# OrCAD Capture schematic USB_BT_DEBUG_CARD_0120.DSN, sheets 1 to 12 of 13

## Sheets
1 PAGE01 TITLE: rev: A
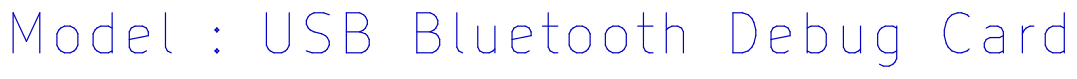
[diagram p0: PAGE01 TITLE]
2 PAGE02 INDEX
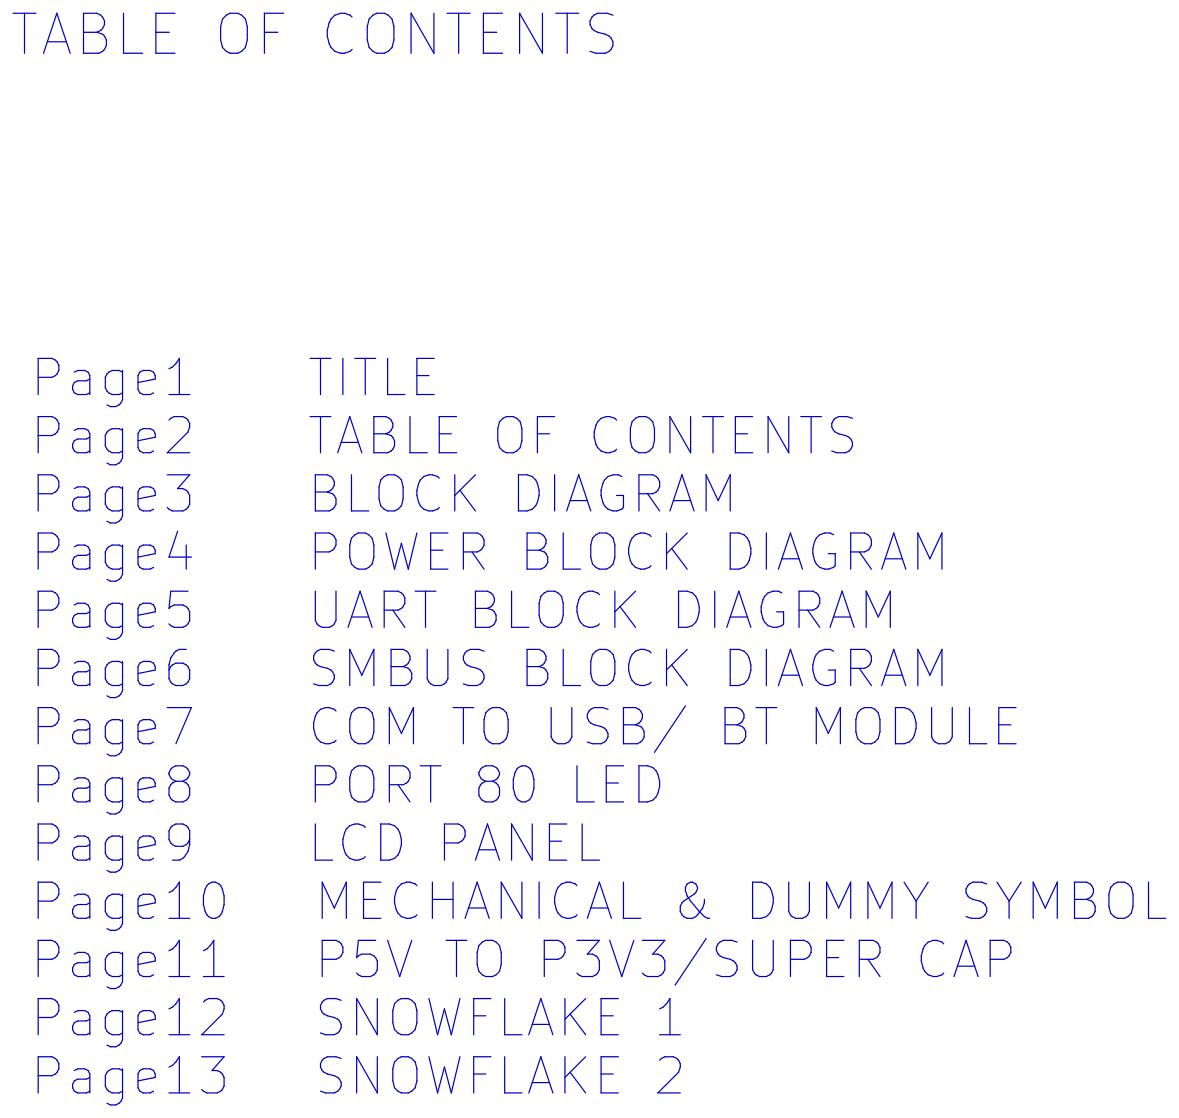
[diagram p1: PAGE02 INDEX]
3 PAGE03 BLOCK DIAGRAM
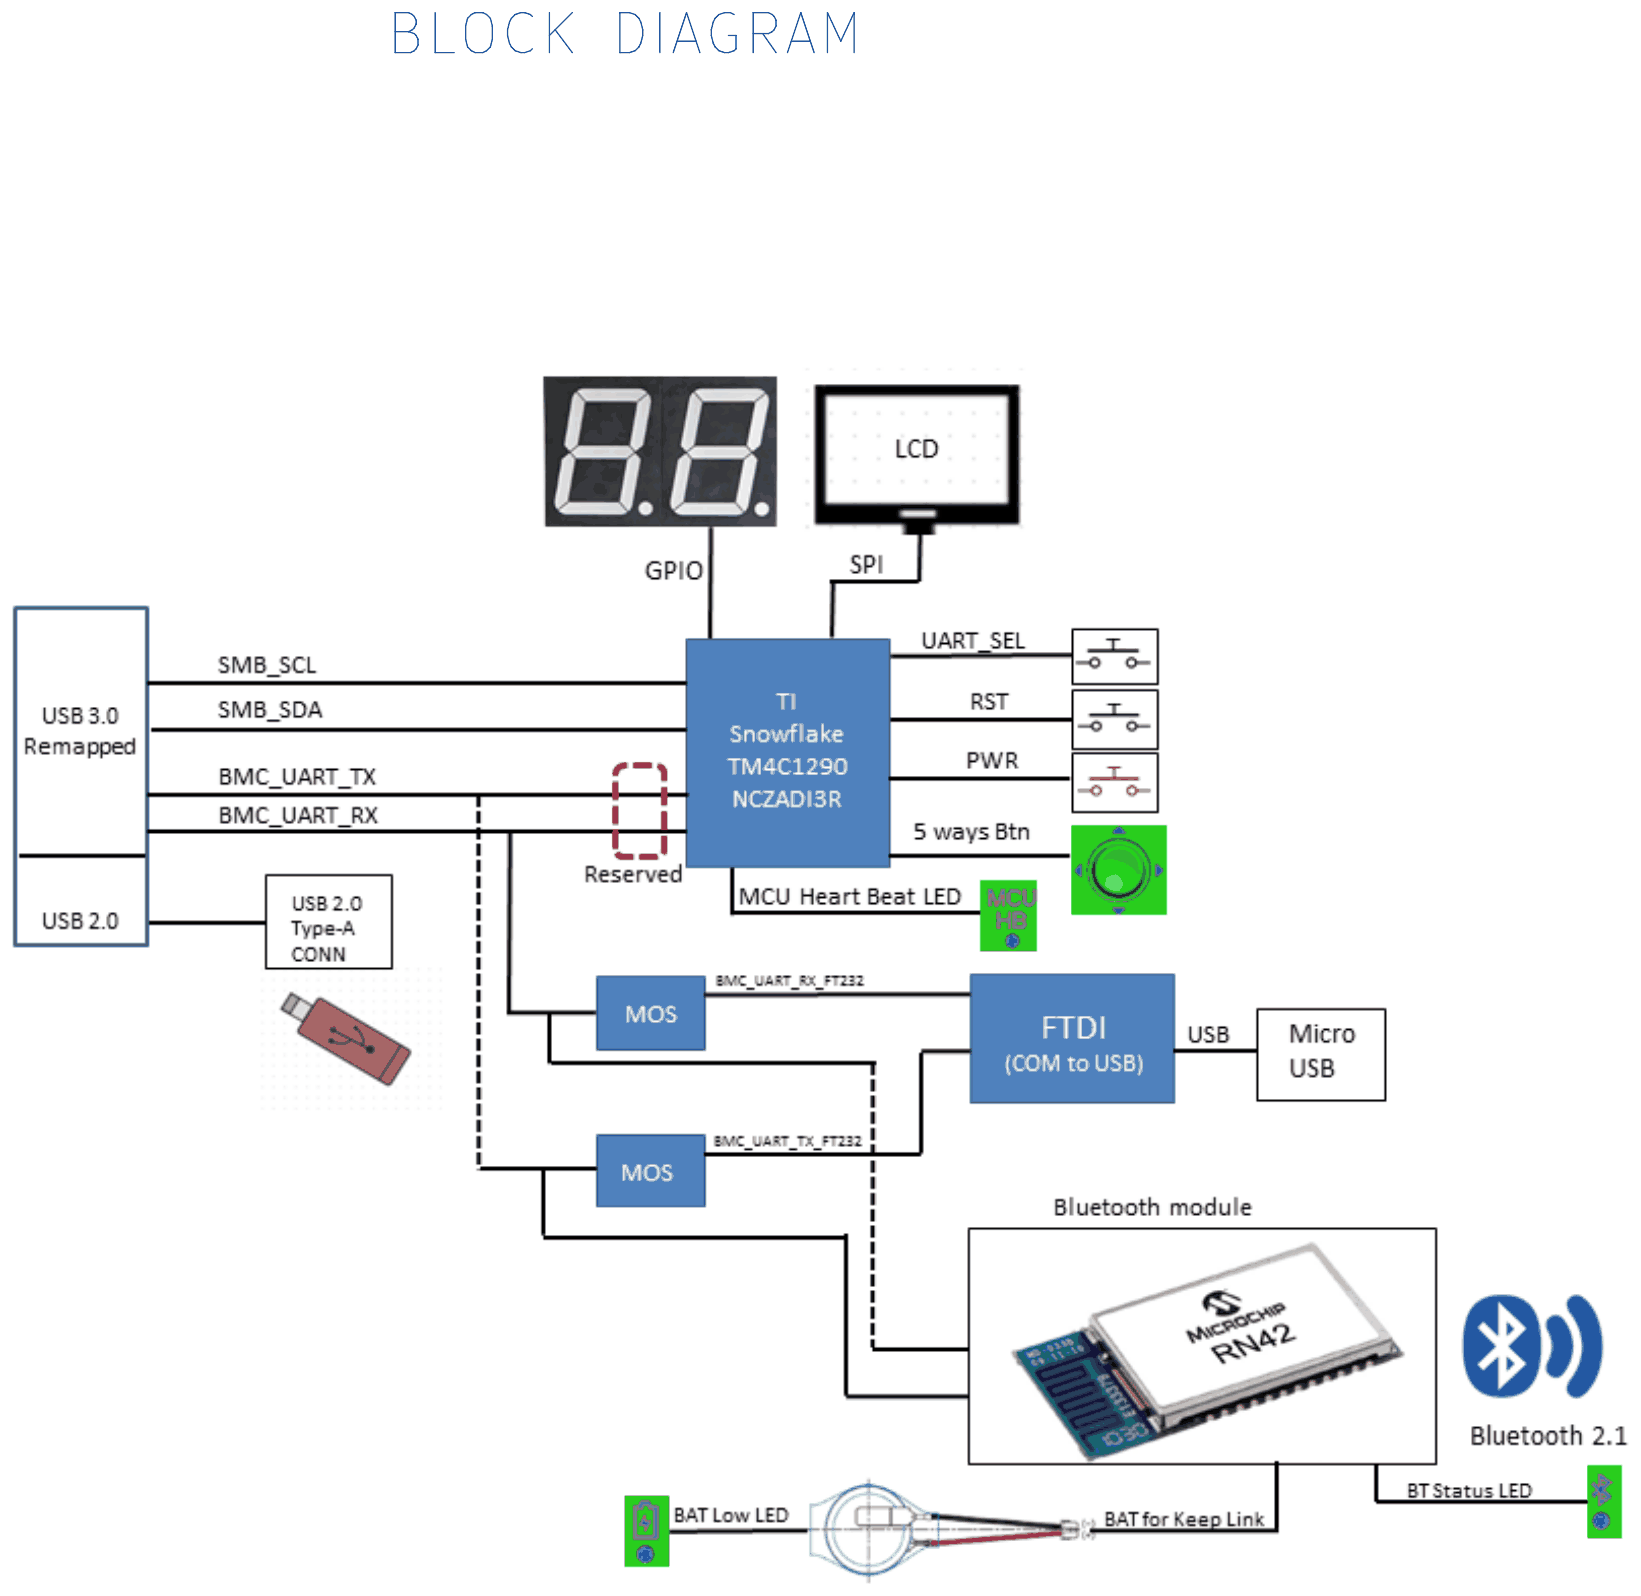
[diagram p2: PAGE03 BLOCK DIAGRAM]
4 PAGE04 POWER BLOCK DIAGRAM
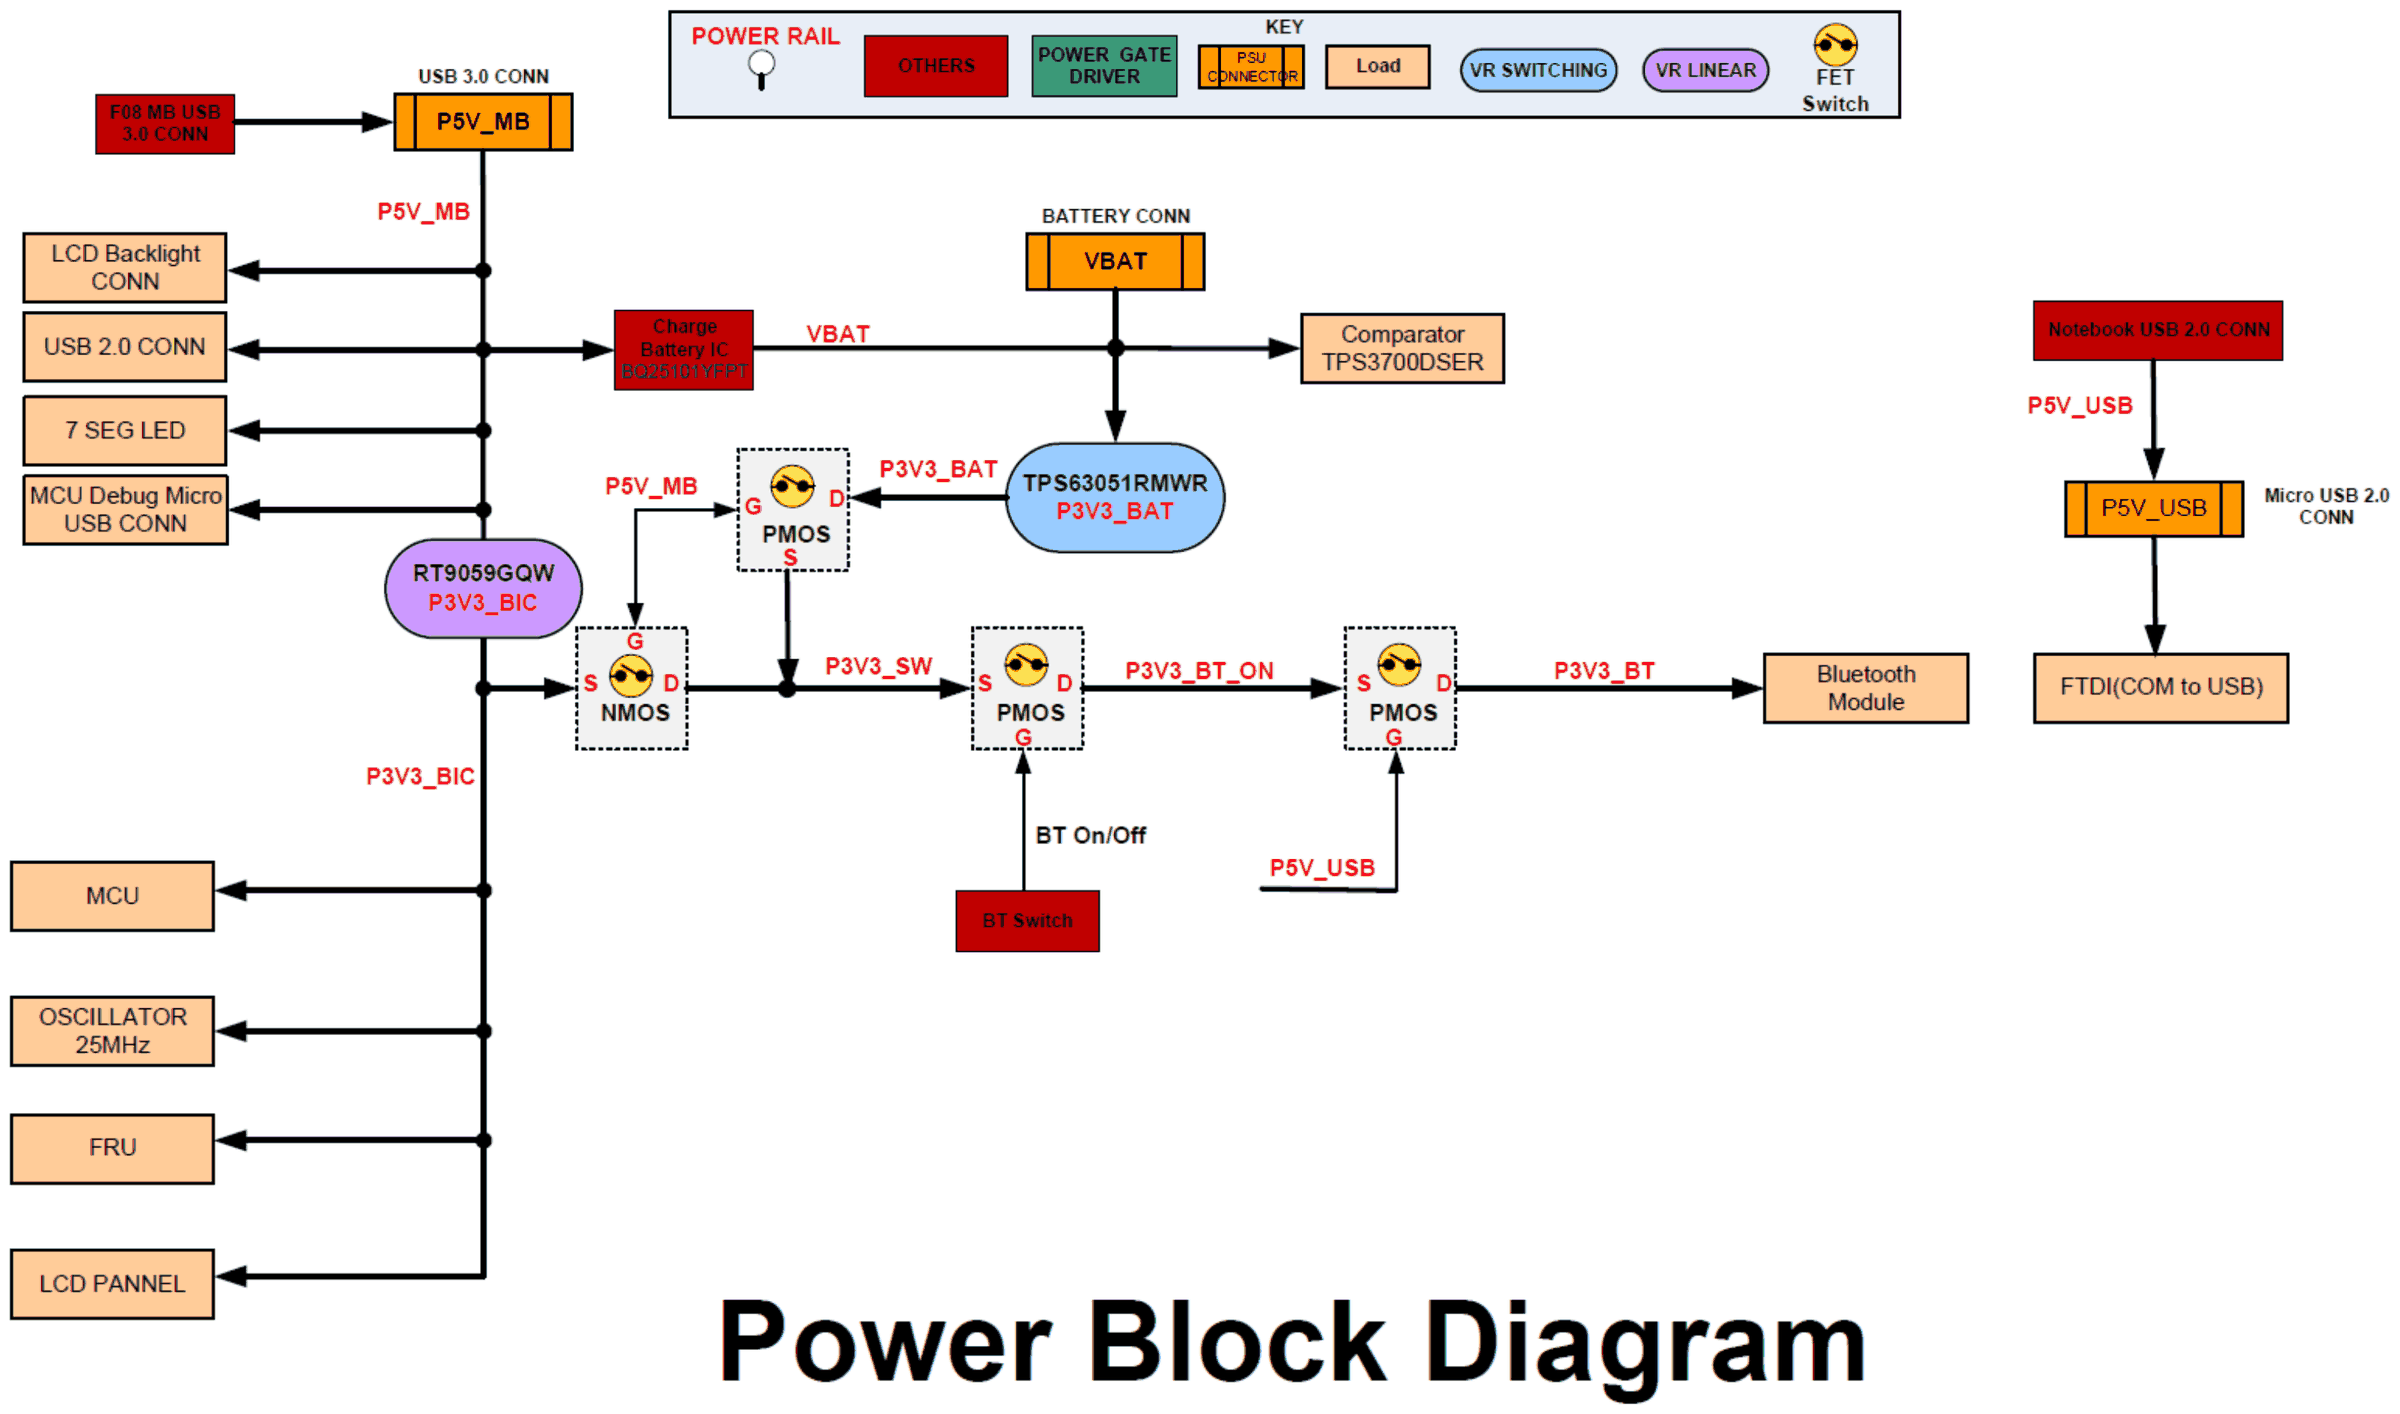
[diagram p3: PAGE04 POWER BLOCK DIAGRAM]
5 PAGE05 UART BLOCK DIAGRAM
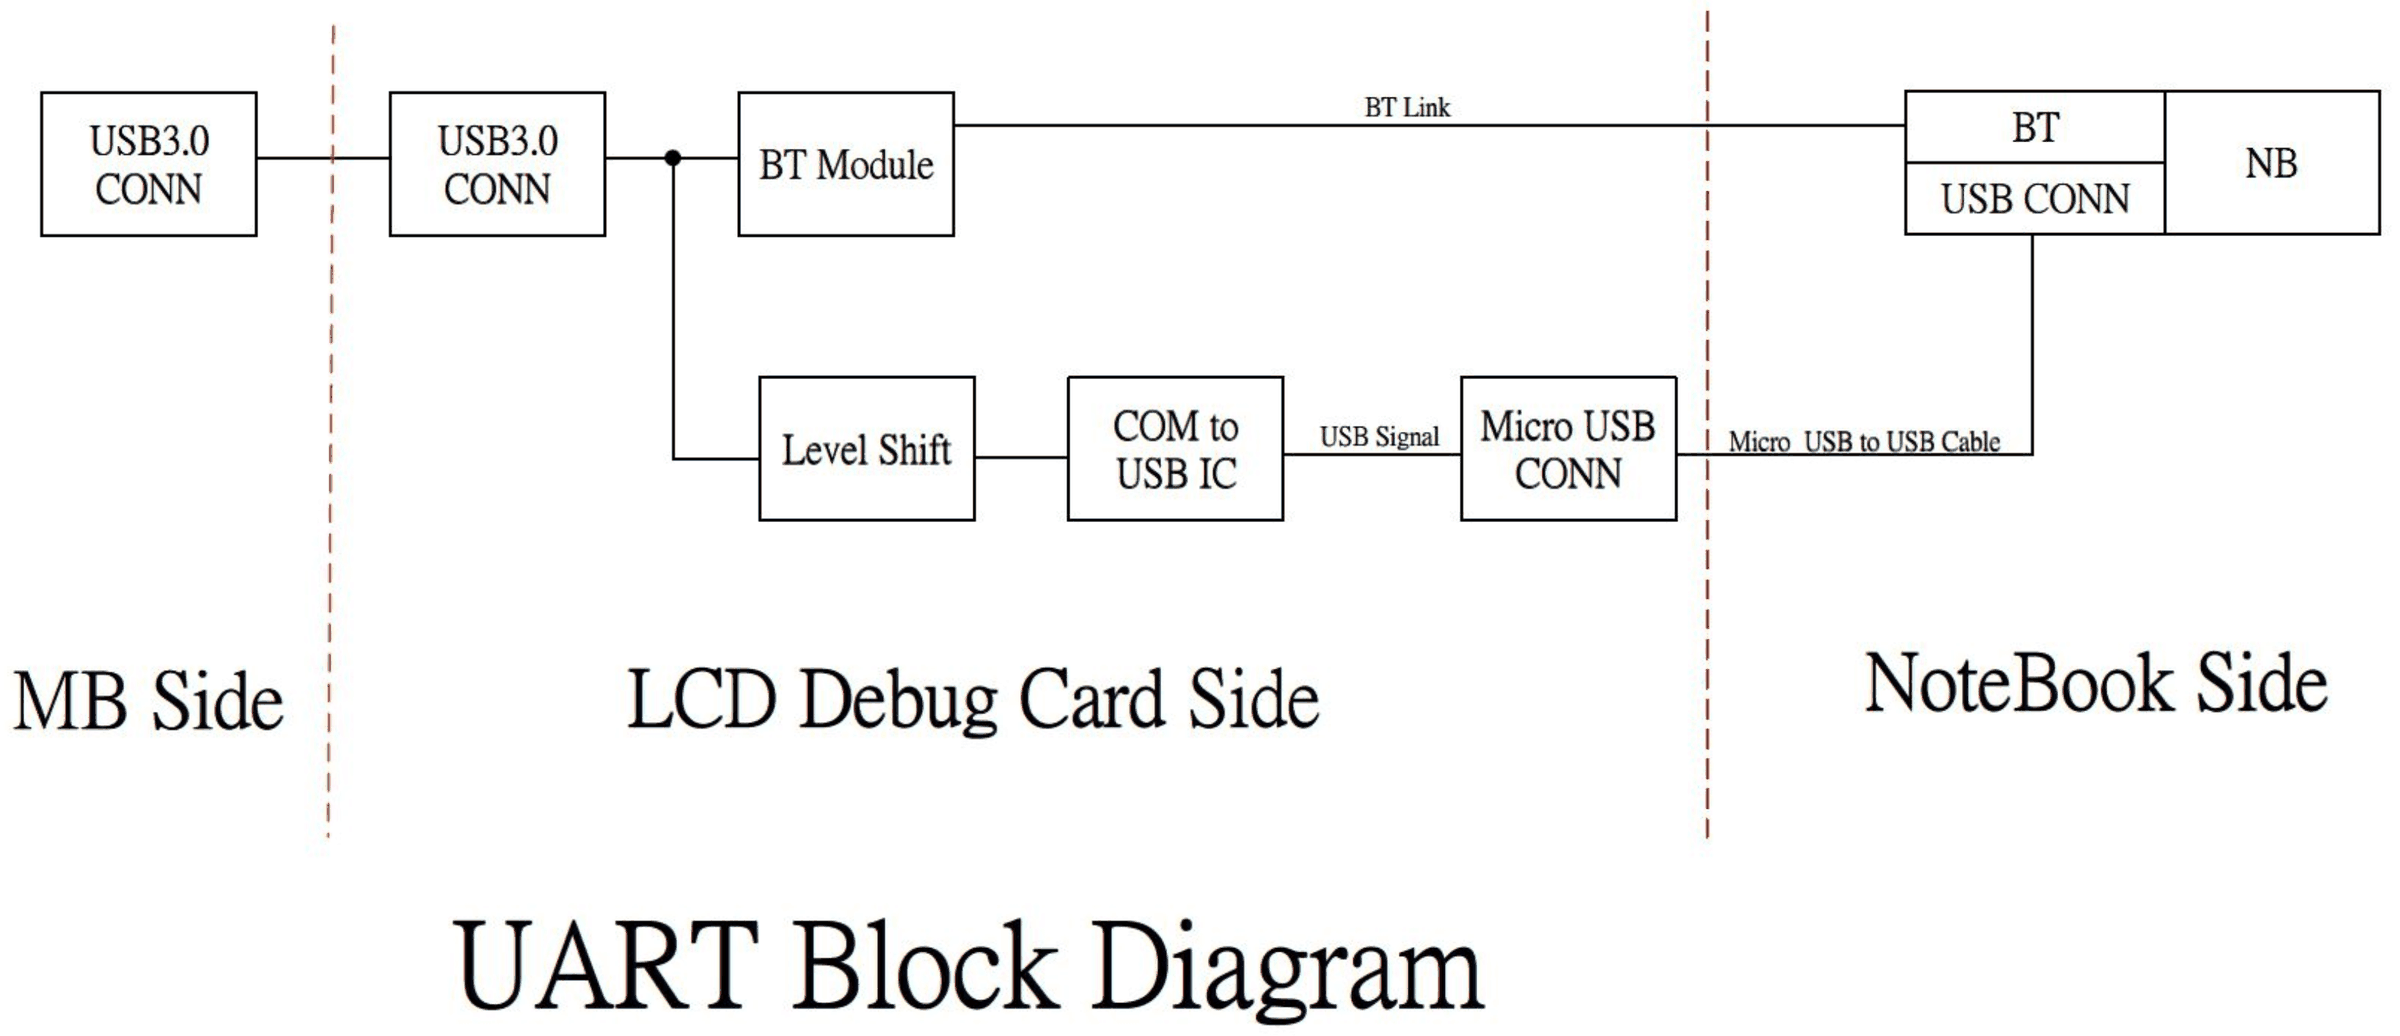
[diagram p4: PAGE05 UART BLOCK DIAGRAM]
6 PAGE06 SMBUS BLOCK DIAGRAM
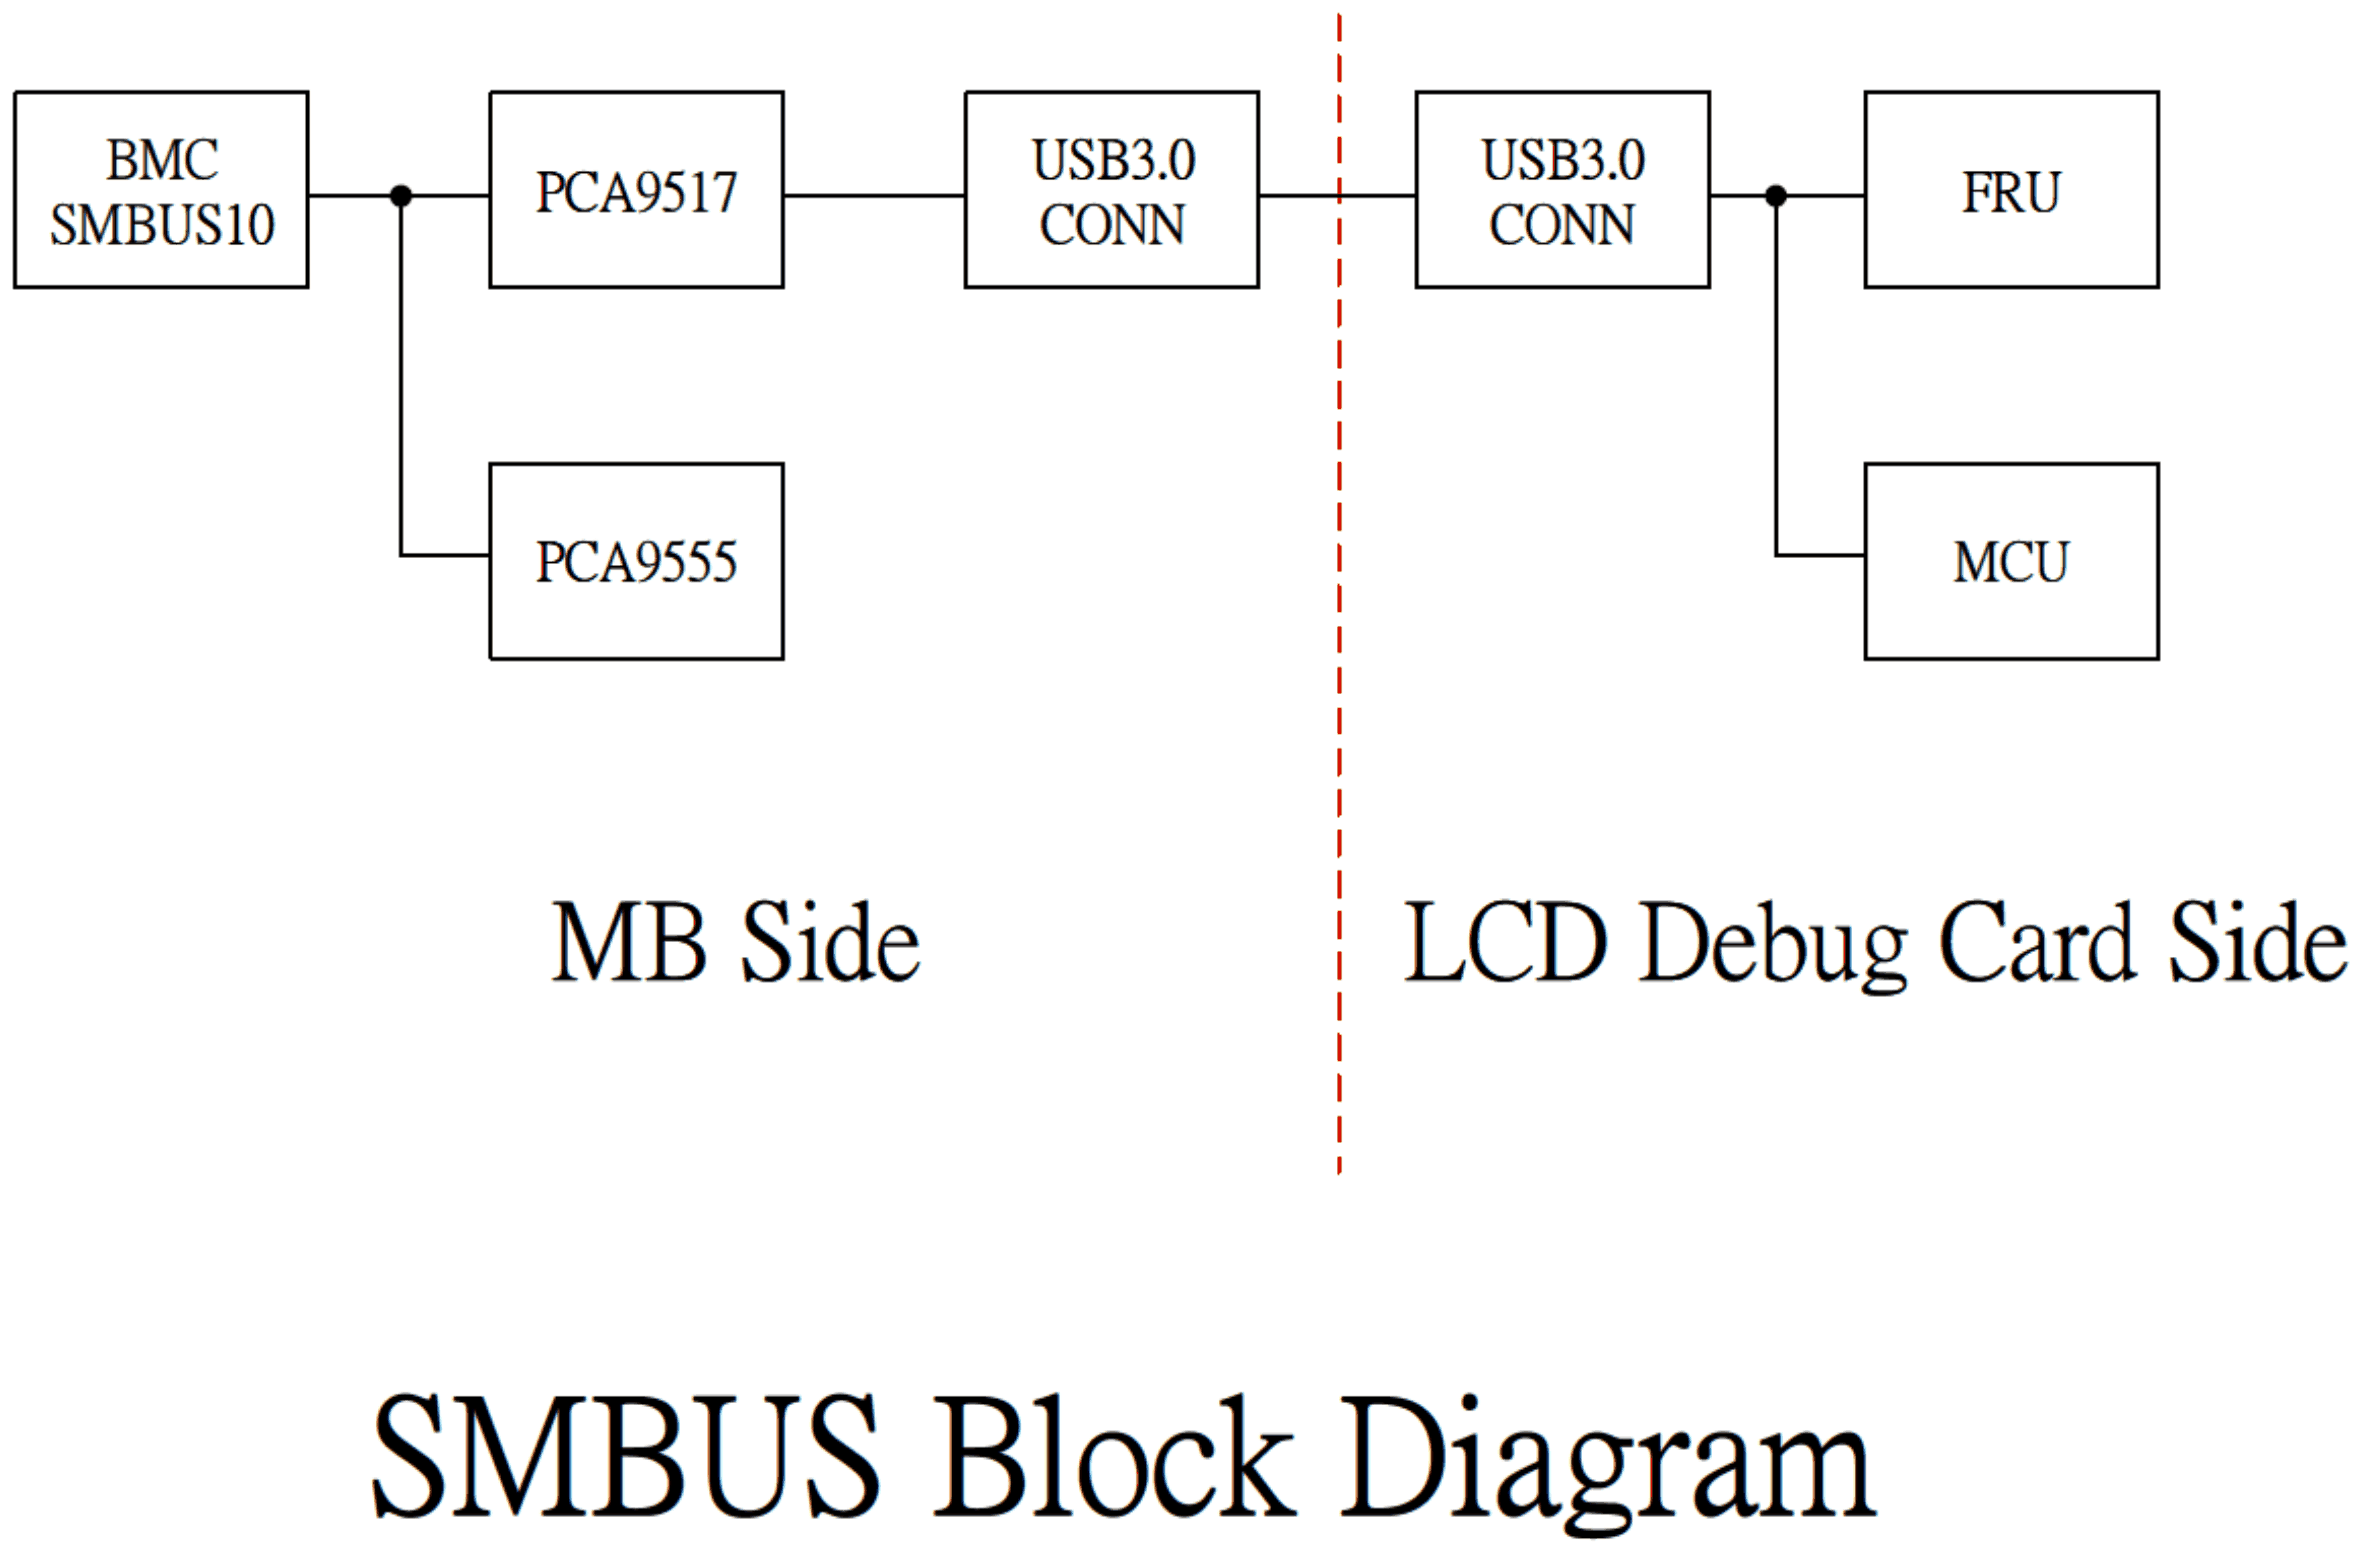
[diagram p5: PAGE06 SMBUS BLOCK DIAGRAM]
7 PAGE08 CPLD MCU: size A3
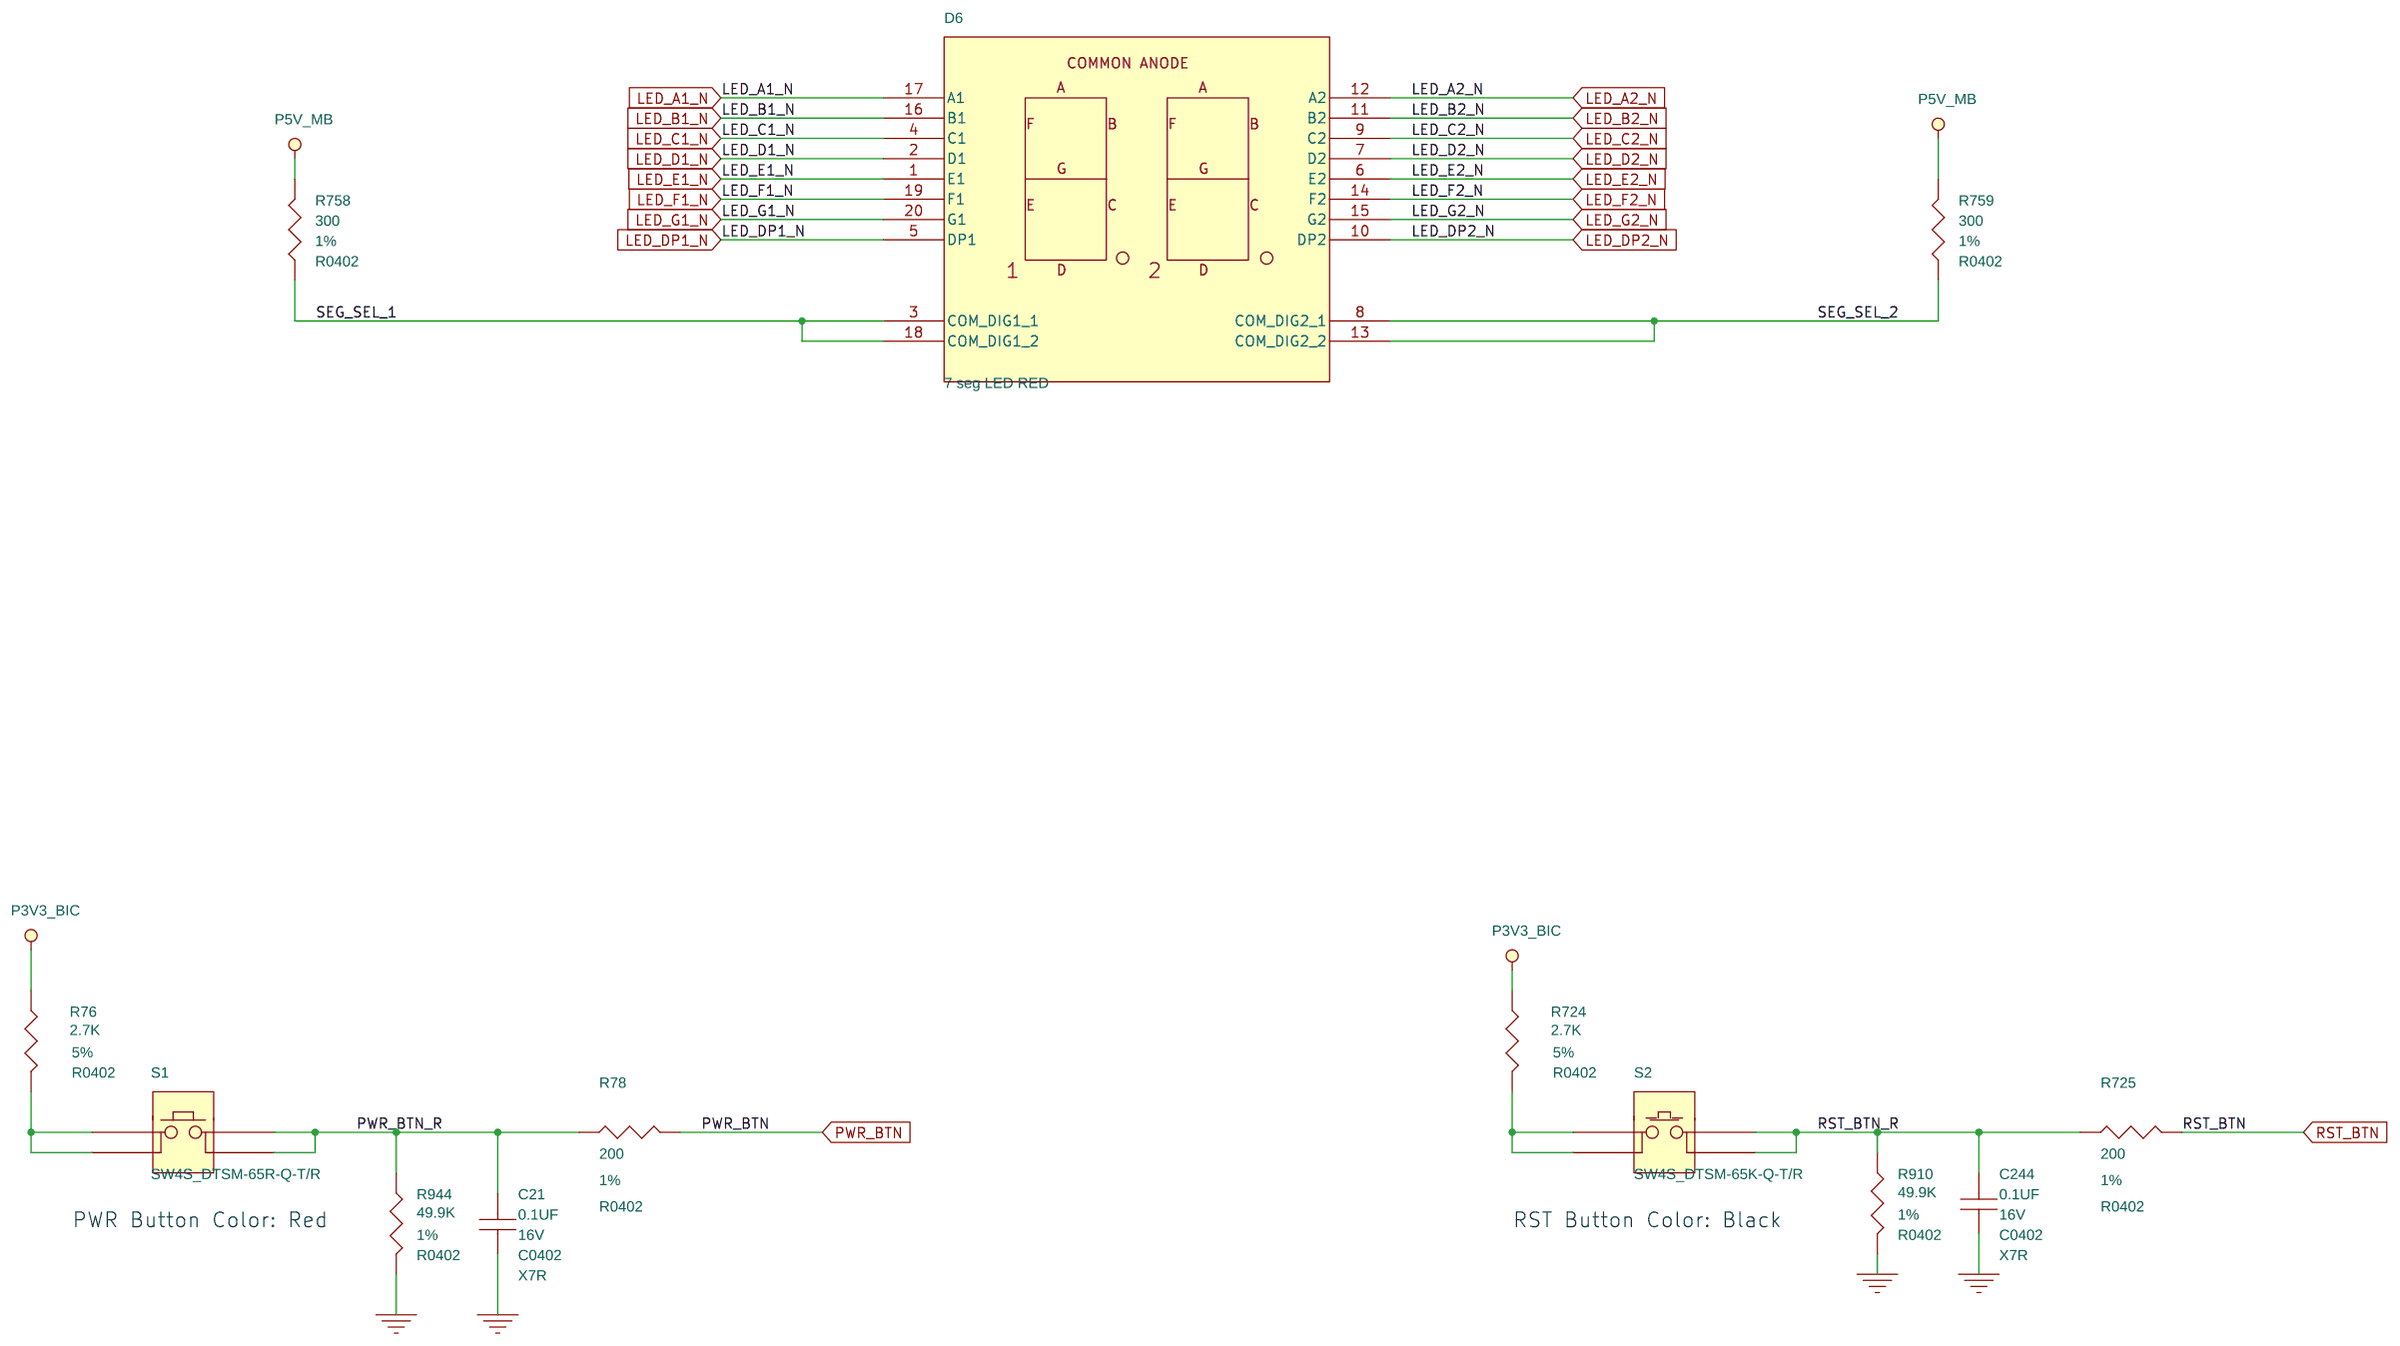
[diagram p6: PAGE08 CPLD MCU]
8 PAGE09 LCD: size A3
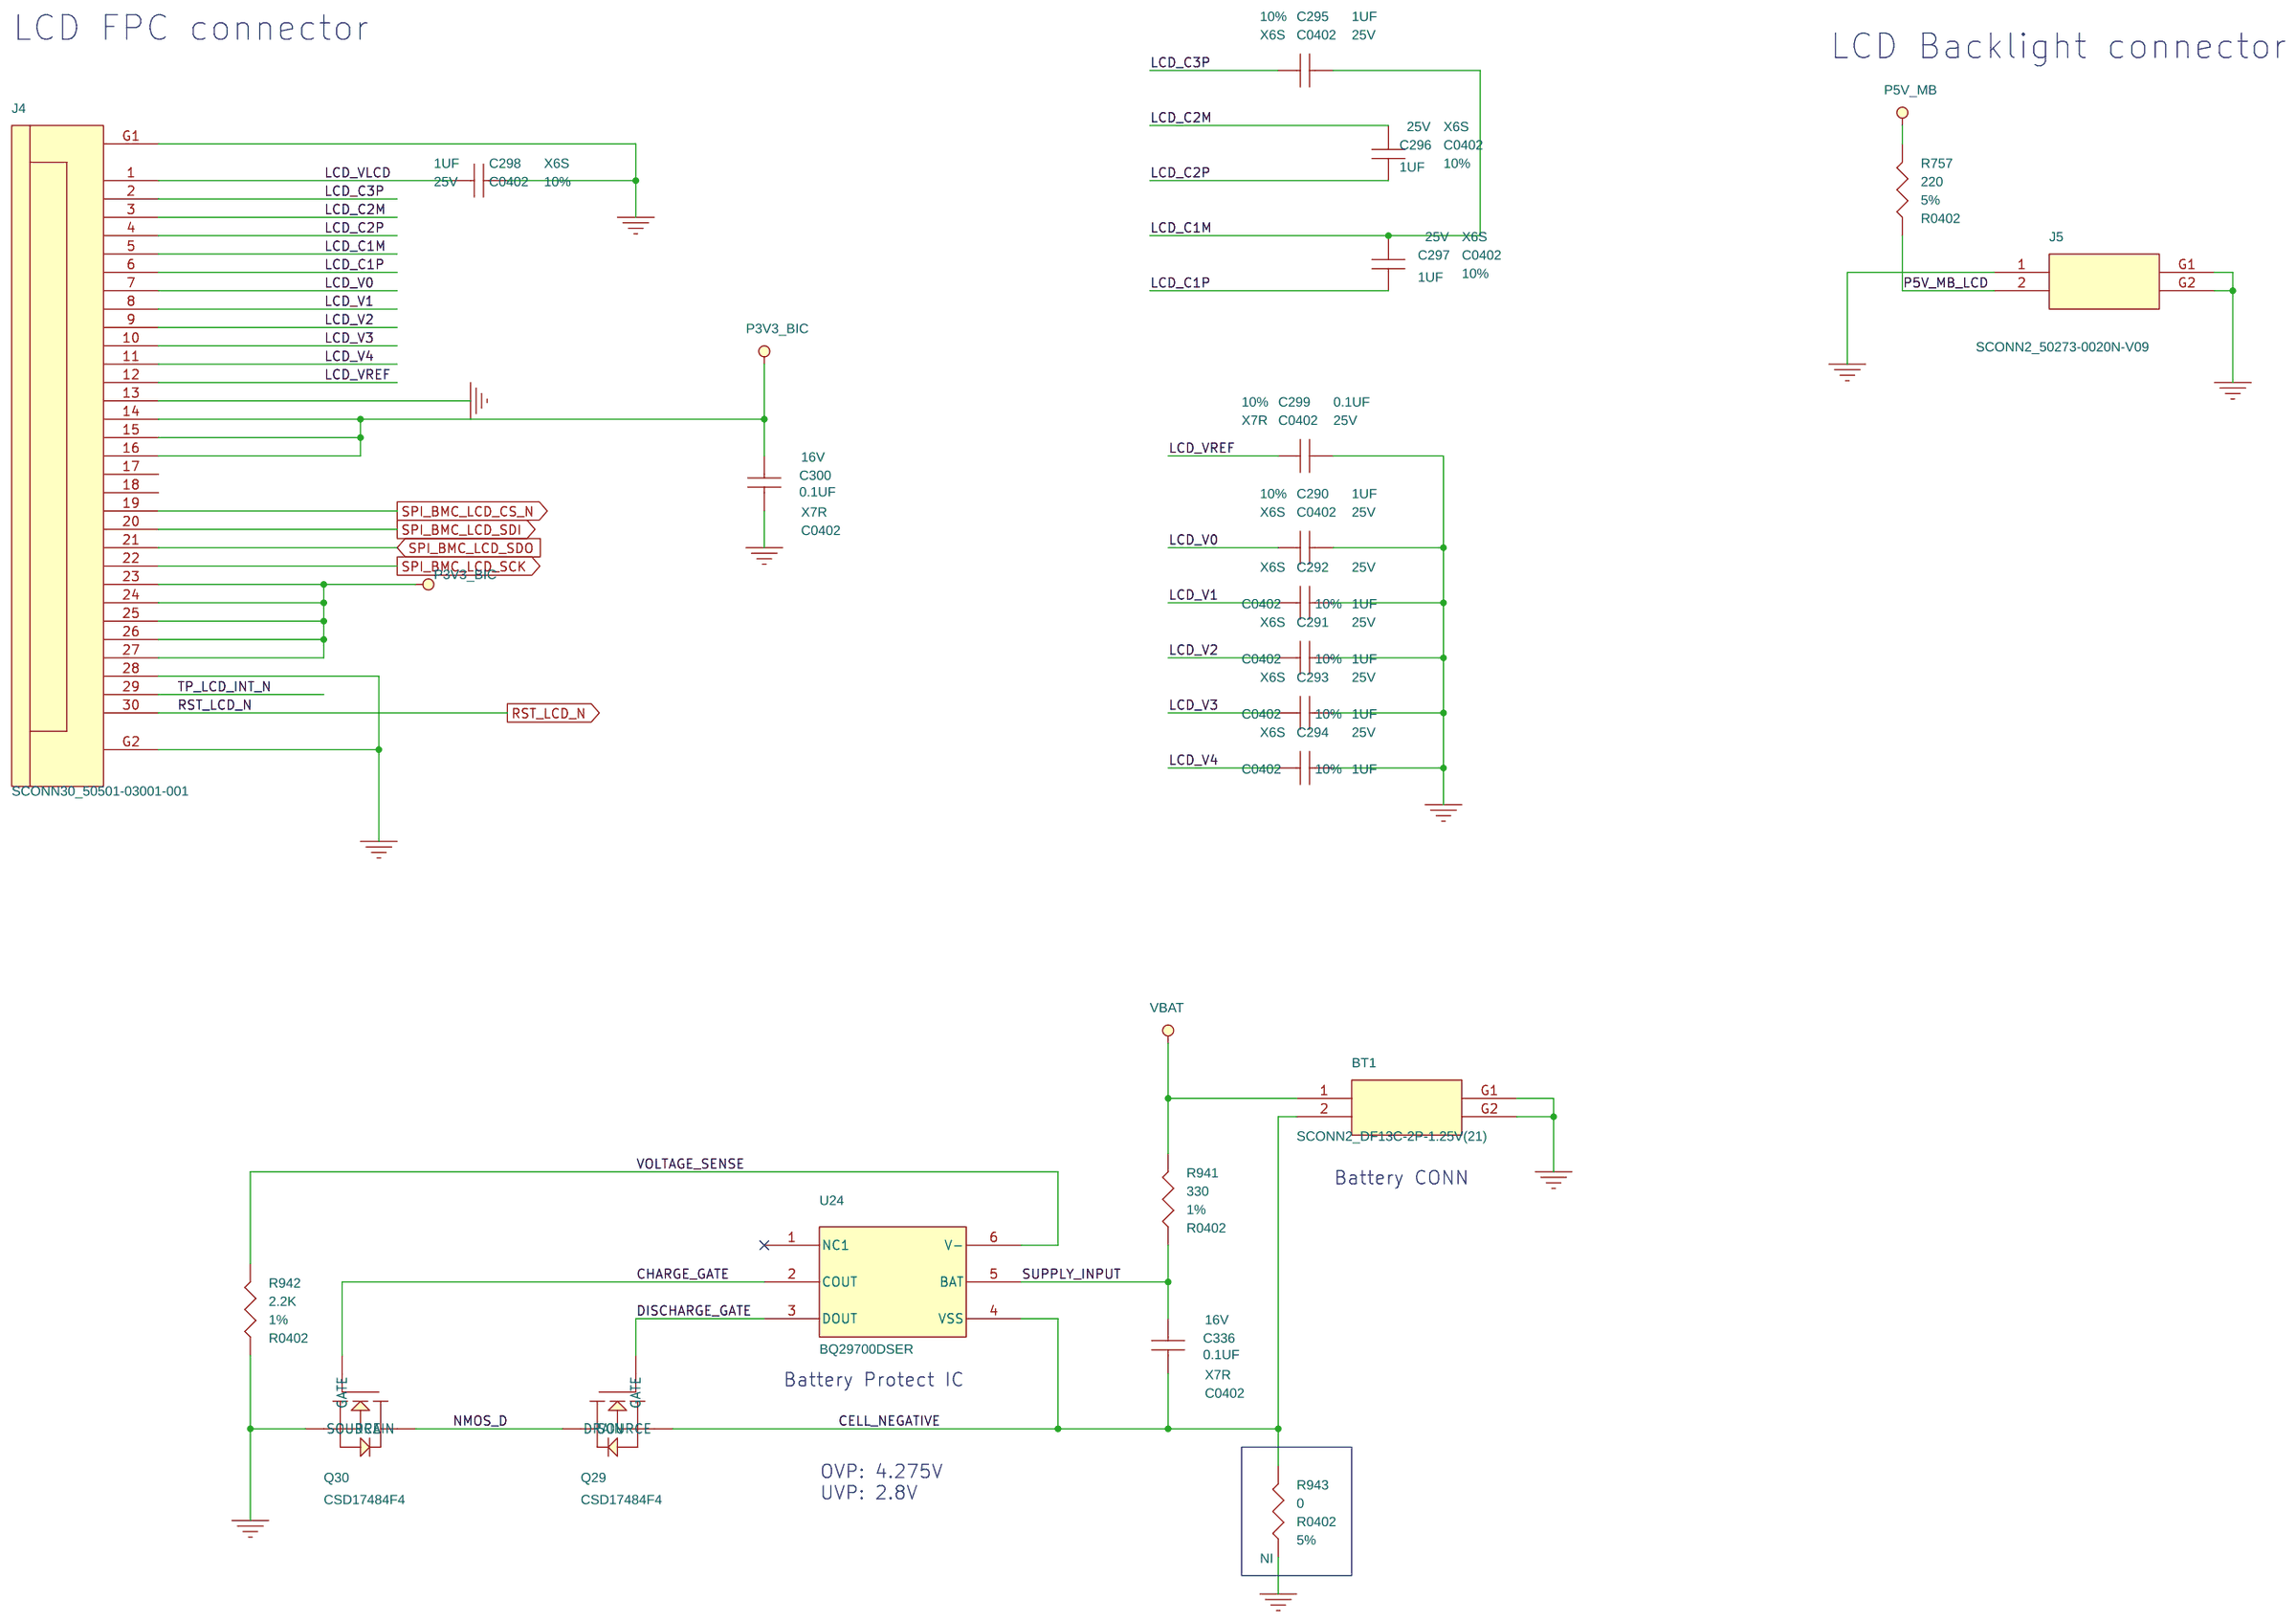
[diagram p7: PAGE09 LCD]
9 PAGE12 SNOWFLAKE1: size A3; rev: 0.01
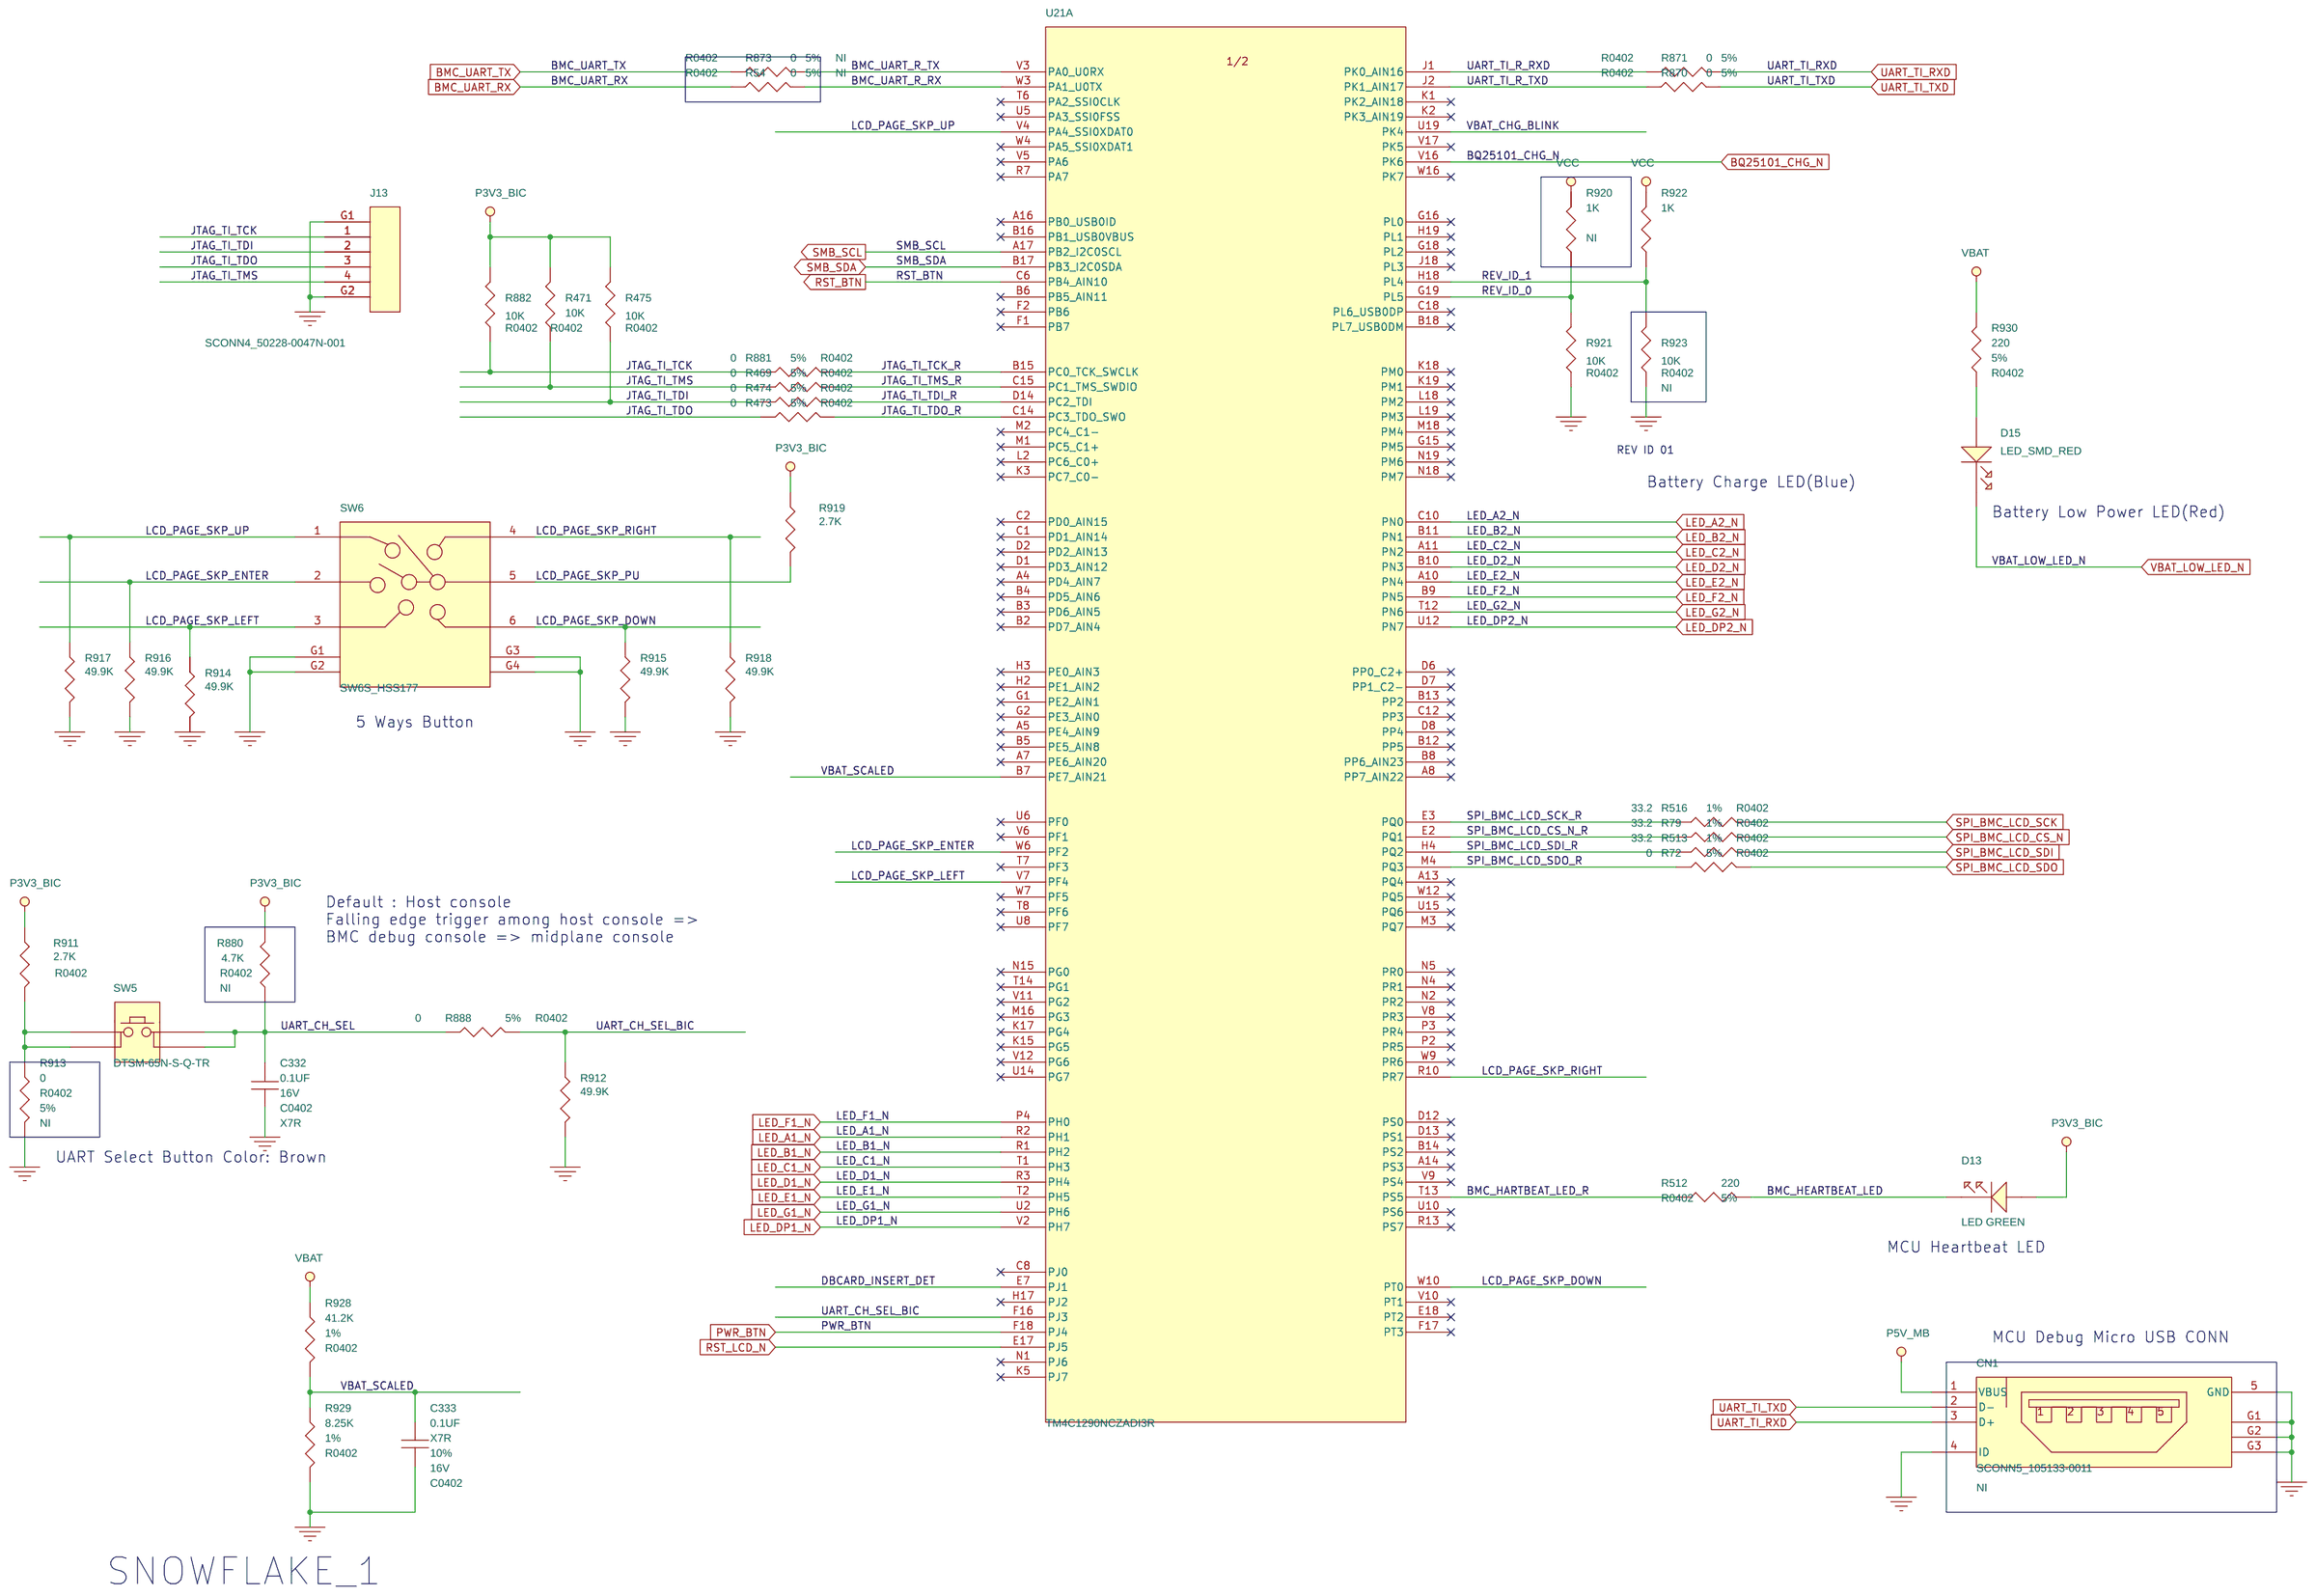
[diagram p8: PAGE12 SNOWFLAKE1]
10 PAGE13 SNOWFLAKE2: size A3; rev: 0.01
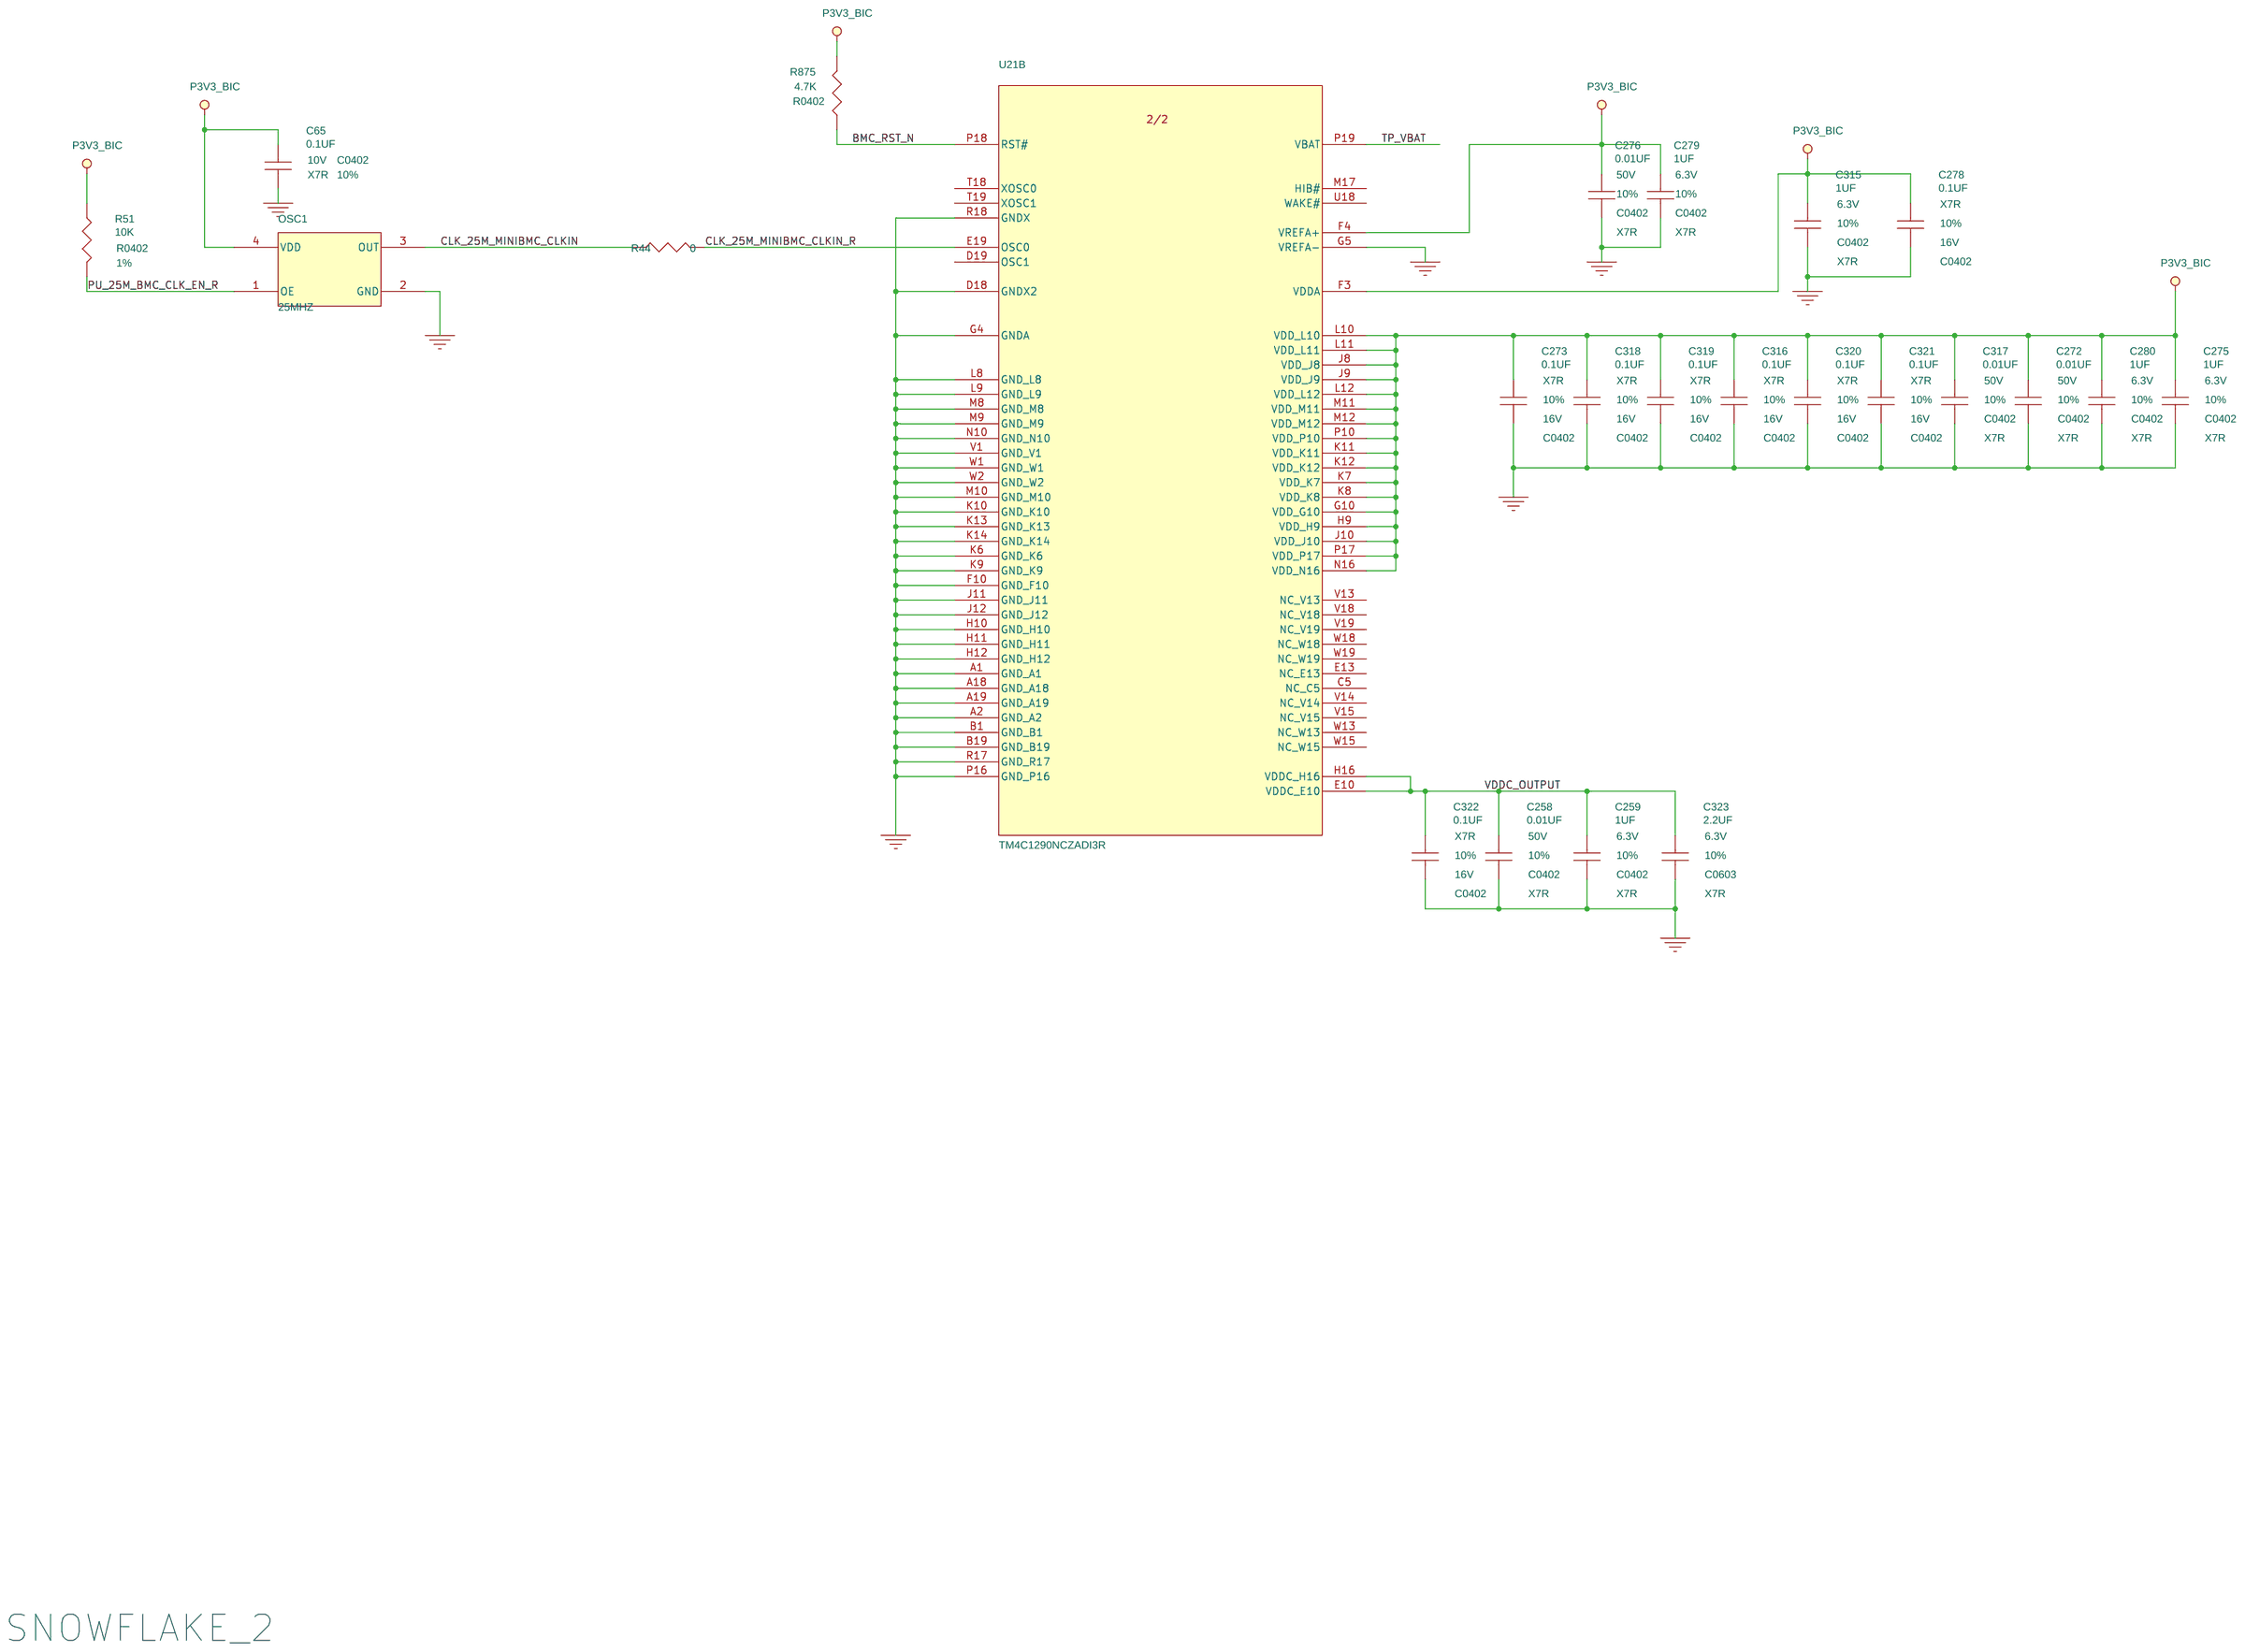
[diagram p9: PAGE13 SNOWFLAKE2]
11 PAGE10 MECHANICAL/DUMMY: size A3
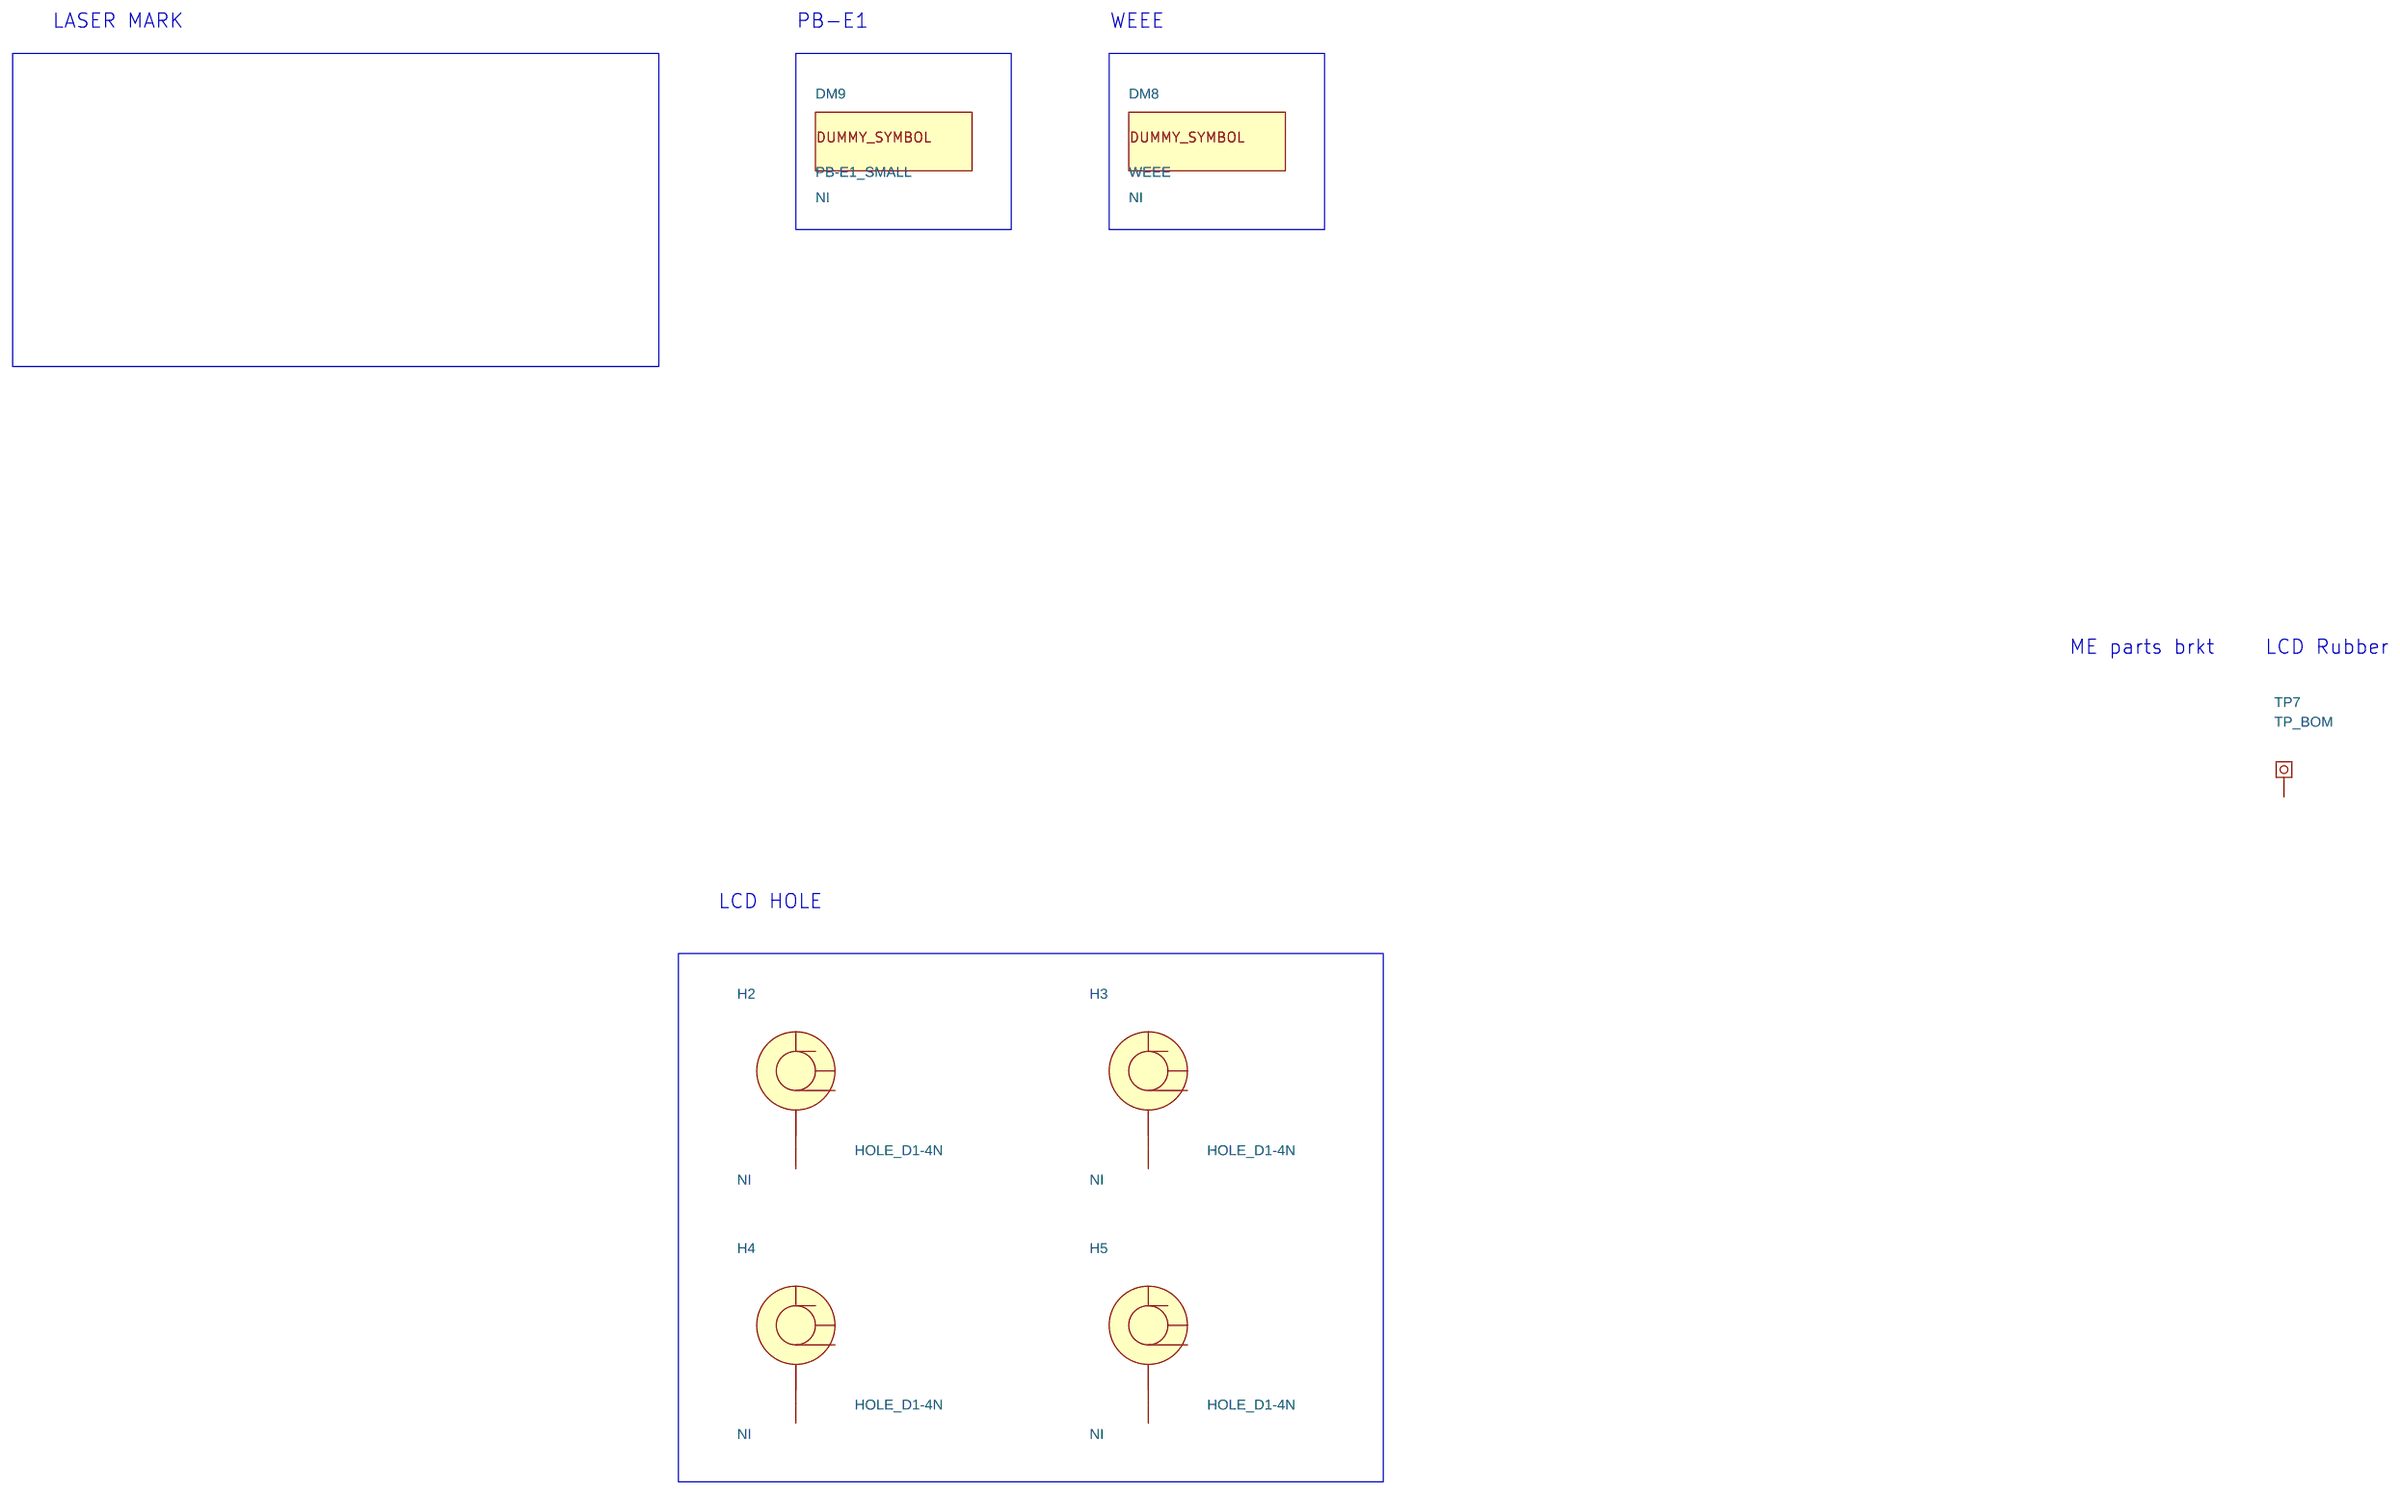
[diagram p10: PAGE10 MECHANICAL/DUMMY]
12 PAGE07 COM to USB/BT module: size A3
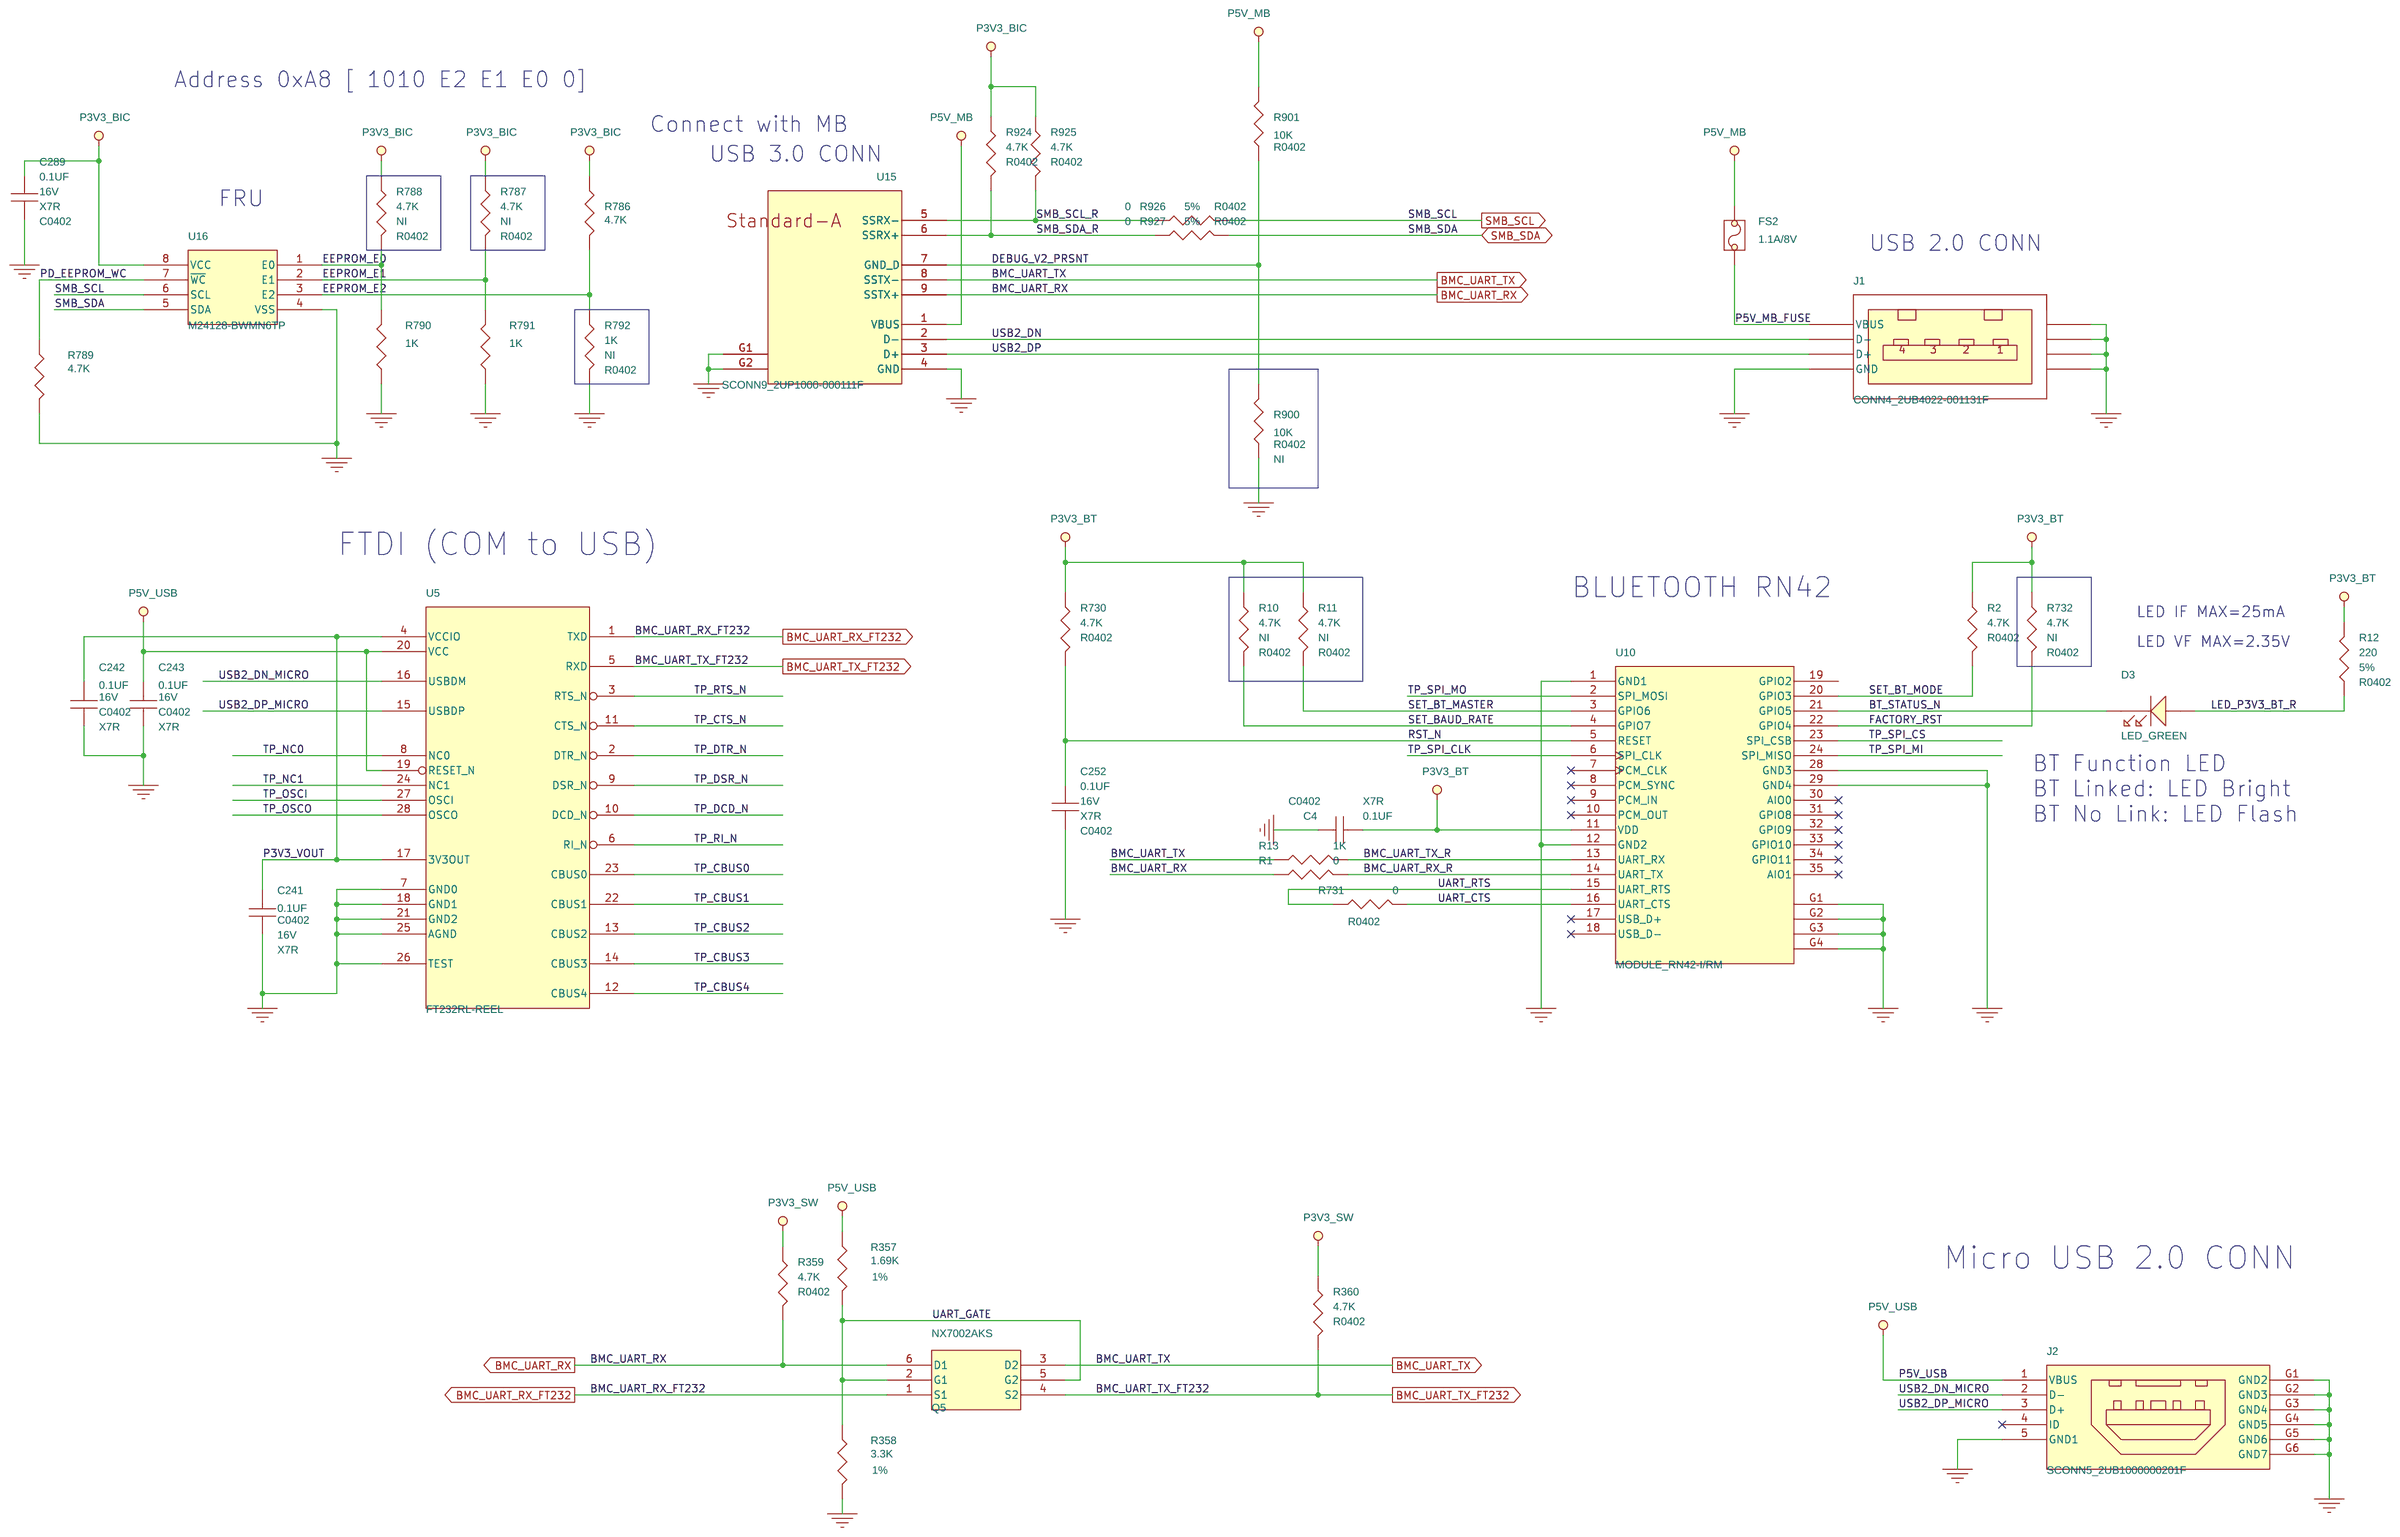
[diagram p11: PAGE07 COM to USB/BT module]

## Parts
sheet PAGE07 COM to USB/BT module
C4  0.1UF  [C0402]
C241  0.1UF  [C0402]
C242  0.1UF  [C0402]
C243  0.1UF  [C0402]
C252  0.1UF  [C0402]
C289  0.1UF  [C0402]
D3  LED_GREEN  [LED_1921]
FS2  1.1A/8V  [F1206]
J1  CONN4_2UB4022-001131F  [USB1XBE]
J2  SCONN5_2UB1000000201F  [USB1XAK]
Q5  NX7002AKS  [SOT363XB]
R1  0  [R0402]
R2  4.7K  [R0402]
R10  4.7K  [R0402]
R11  4.7K  [R0402]
R12  220  [R0402]
R13  1K  [R0402]
R357  1.69K  [R0402]
R358  3.3K  [R0402]
R359  4.7K  [R0402]
R360  4.7K  [R0402]
R730  4.7K  [R0402]
R731  0  [R0402]
R732  4.7K  [R0402]
R786  4.7K  [R0402]
R787  4.7K  [R0402]
R788  4.7K  [R0402]
R789  4.7K  [R0402]
R790  1K  [R0402]
R791  1K  [R0402]
R792  1K  [R0402]
R900  10K  [R0402]
R901  10K  [R0402]
R924  4.7K  [R0402]
R925  4.7K  [R0402]
R926  0  [R0402]
R927  0  [R0402]
U5  FT232RL-REEL  [SSOP28_0-65_10-2X5-3]
U10  MODULE_RN42-I/RM  [BLUETOOTH35S]
U15  SCONN9_2UP1000-000111F  [USB1XBF]
U16  M24128-BWMN6TP  [SOIC8XH]
sheet PAGE08 CPLD MCU
C21  0.1UF  [C0402]
C244  0.1UF  [C0402]
D6  7 seg LED RED  [LED20S_LTD-3813CKD-P]
R76  2.7K  [R0402]
R78  200  [R0402]
R724  2.7K  [R0402]
R725  200  [R0402]
R758  300  [R0402]
R759  300  [R0402]
R910  49.9K  [R0402]
R944  49.9K  [R0402]
S1  SW4S_DTSM-65R-Q-T/R  [SW4S_DTSM-65N]
S2  SW4S_DTSM-65K-Q-T/R  [SW4S_DTSM-65N]
sheet PAGE09 LCD
BT1  SCONN2_DF13C-2P-1.25V(21)  [CON_2S1H2S_P1-25XC]
C290  1UF  [C0402]
C291  1UF  [C0402]
C292  1UF  [C0402]
C293  1UF  [C0402]
C294  1UF  [C0402]
C295  1UF  [C0402]
C296  1UF  [C0402]
C297  1UF  [C0402]
C298  1UF  [C0402]
C299  0.1UF  [C0402]
C300  0.1UF  [C0402]
C336  0.1UF  [C0402]
J4  SCONN30_50501-03001-001  [CON_30S1H2S_P0-5XC]
J5  SCONN2_50273-0020N-V09  [CON_2S1H2S_P1-25XA]
Q29  CSD17484F4  [PICOSTAR_GDS]
Q30  CSD17484F4  [PICOSTAR_GDS]
R757  220  [R0402]
R941  330  [R0402]
R942  2.2K  [R0402]
R943  0  [R0402]
U24  BQ29700DSER  [WSON6_0-5_1-5X1-5XA]
sheet PAGE10 MECHANICAL/DUMMY
DM8  WEEE  [WEEE]
DM9  PB-E1_SMALL  [PB-E1_SMALL]
H2  HOLE_D1-4N  [HOLE_D1-4N]
H3  HOLE_D1-4N  [HOLE_D1-4N]
H4  HOLE_D1-4N  [HOLE_D1-4N]
H5  HOLE_D1-4N  [HOLE_D1-4N]
TP7  TP_BOM  [TP30]
sheet PAGE12 SNOWFLAKE1
C332  0.1UF  [C0402]
C333  0.1UF  [C0402]
CN1  SCONN5_105133-0011  [USB1XAY]
D13  LED GREEN  [LED2S_0402]
D15  LED_SMD_RED  [LED_1921]
J13  SCONN4_50228-0047N-001  [CON_4S1H2S_P1XA]
R54  0  [R0402]
R72  0  [R0402]
R79  33.2  [R0402]
R469  0  [R0402]
R471  10K  [R0402]
R473  0  [R0402]
R474  0  [R0402]
R475  10K  [R0402]
R512  220  [R0402]
R513  33.2  [R0402]
R516  33.2  [R0402]
R870  0  [R0402]
R871  0  [R0402]
R873  0  [R0402]
R880  4.7K  [R0402]
R881  0  [R0402]
R882  10K  [R0402]
R888  0  [R0402]
R911  2.7K  [R0402]
R912  49.9K  [R0402]
R913  0  [R0402]
R914  49.9K  [R0402]
R915  49.9K  [R0402]
R916  49.9K  [R0402]
R917  49.9K  [R0402]
R918  49.9K  [R0402]
R919  2.7K  [R0402]
R920  1K  [R0402]
R921  10K  [R0402]
R922  1K  [R0402]
R923  10K  [R0402]
R928  41.2K  [R0402]
R929  8.25K  [R0402]
R930  220  [R0402]
SW5  DTSM-65N-S-Q-TR  [SW_DTSM-62N-S-V-TR]
SW6  SW6S_HSS177  [SW6S_HSS177]
sheet PAGE13 SNOWFLAKE2
C65  0.1UF  [C0402]
C258  0.01UF  [C0402]
C259  1UF  [C0402]
C272  0.01UF  [C0402]
C273  0.1UF  [C0402]
C275  1UF  [C0402]
C276  0.01UF  [C0402]
C278  0.1UF  [C0402]
C279  1UF  [C0402]
C280  1UF  [C0402]
C315  1UF  [C0402]
C316  0.1UF  [C0402]
C317  0.01UF  [C0402]
C318  0.1UF  [C0402]
C319  0.1UF  [C0402]
C320  0.1UF  [C0402]
C321  0.1UF  [C0402]
C322  0.1UF  [C0402]
C323  2.2UF  [C0603]
OSC1  25MHZ  [OSC4_FJ2500009]
R44  0  [R0402]
R51  10K  [R0402]
R875  4.7K  [R0402]
U21  TM4C1290NCZADI3R  [BGA212]  (sections A,B)

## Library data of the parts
C4 C252 = CAP_NP: CAP CHIP 0.1U 16V(10%.X7R.0402); CLASS: DISCRETE; CMPLS_LVL: EP; Data: MUR_LF_CAP SERIES_1.pdf; From_pj: S10-ANTONY; Lifecycle: Comp-Approve; MATERIAL: X7R; Manuf_PN: GRM155R71C104K; Manuf_name: MURATA ERIE N.A. INC TAIWAN BRANCH Okayama Murata Mfg.Co..Ltd. Wakura Murata Mfg; Manuftr: MUR; Part_Type: *LF_C0402; Standard: ##; Status: Preferred; TOLERANCE: 10%; TOP_BOT: BOT; VOLTAGE: 16V
C21 C241-C243 C332 = CAP_NP: CAP CHIP 0.1U 16V(10%,X7R,0402); CLASS: DISCRETE; CMPLS_LVL: EP; Data: MUR_LF_CAP SERIES_1.pdf; From_pj: S10-ANTONY; MATERIAL: X7R; Manuf_PN: GRM155R71C104K; Manuf_name: MURATA ERIE N.A. INC TAIWAN BRANCH Okayama Murata Mfg.Co.,Ltd. Wakura Murata Mfg; Manufacturer: MUR; Part_Type: *LF_C0402; Status: Preferred; TOLERANCE: 10%; TOP_BOT: BOT; VOLTAGE: 16V
C289 = CAP_NP: CAP CHIP 0.1U 16V(10%.X7R.0402); CLASS: DISCRETE; CMPLS_LVL: EP; Data: MUR_LF_CAP SERIES_1.pdf; From_pj: S10-ANTONY; Lifecycle: Comp-Approve; MATERIAL: X7R; Manuf_PN: GRM155R71C104K; Manuf_name: MURATA ERIE N.A. INC TAIWAN BRANCH Okayama Murata Mfg.Co..Ltd. Wakura Murata Mfg; Manuftr: MUR; Part_Type: *LF_C0402; Standard: ##; Status: Preferred; TOLERANCE: 10%; TOP_BOT: TOP; VOLTAGE: 16V
D3 = LED_0: LED SMD(2P) GREEN(19-213/GVC-AMNB/3T); CLASS: IC; CMPLS_LVL: EP(V1); Data: EVL_19-213-GVC-AMNB-3T.pdf; From_pj: S5A-ROGER; Lifecycle: Comp-Approve; MATERIAL: IC; Manuf_PN: 19-213/GVC-AMNB/3T; Manuf_name: EVERLIGHT (EVERLIGHT ELECTRONICS CO., LTD. ); Manuftr: EVL; Part_Type: *LF_Semiconductor; RD_CMPLS_LVL: EP(V1); TOP_BOT: TOP
FS2 = FUSE: FUSE SMD 1.1A 8V POLY(SMD1206P110TFT); CLASS: IO; CMPLS_LVL: EP(V1); Data: PYS_SMD1206P110TFT.pdf; From_pj: S1D-OZ; Lifecycle: Comp-Approve; MATERIAL: MISC; Manuf_PN: SMD1206P110TFT; Manuf_name: SMD1206P110TFT; Manuftr: PYS; Part_Type: *LF_Misc; RD_CMPLS_LVL: EP(V1); TOP_BOT: BOT; fp_ECN: F1206.doc
J1 = CONN4_2UB4022001131F: CONN DIP HOUSING 4P 1R FR(P2,H6.26); CLASS: IO; DIP_SMD: DIP; Data: SIT_2UB4022-001131F.pdf; From_pj: JBK-WEI-TSUNG; Lifecycle: Comp-Approve; MATERIAL: IO; Manuf_PN: 2UB4022-001131F; Manuf_name: SINGATRON ENTERPRISE CO., LTD. (SINGATRON ELECTRONIC(CHINA) CO., LTD.); Manuftr: SIT; Part_Type: *LF_Connector; RD_CMPLS_LVL: EU(V1); TOP_BOT: BOT
J2 = SCONN5_2UB1000000201F: CONN SMD USB HS 5P 1R FR(P0.65,H2.35); CLASS: IO; CMPLS_LVL: EP(V1); Data: SIT_2UB1000-000201F_REVB.pdf; From_pj: GD1-JOSH; Lifecycle: Comp-Approve; MATERIAL: IO; Manuf_PN: 2UB1000-000201F; Manuf_name: SINGATRON ENTERPRISE CO., LTD.; Manuftr: SIT; Part_Type: *LF_Connector; RD_CMPLS_LVL: EP(V1); Standard: Non-Preferred; TOP_BOT: BOT
Q5 = MOSFET_DUAL_6P: TRANS MOSFET NX7002AKS(60V,170MA,1.06W); CLASS: IC; Data: NXP_NX7002AKS.pdf; From_pj: S1N-AI-JU; Lifecycle: Comp-Approve; MATERIAL: IC; Manuf_name: NXP semiconductors; Manuftr: NXP; Part_Type: *LF_Semiconductor; RD_CMPLS_LVL: EP(V1); Standard: End of Design; TOP_BOT: BOT
R1 R731 = R: RESISTOR CHIP 0 1/16W +-5%(0402); CLASS: DISCRETE; CMPLS_LVL: EP; Data: WTC_LF_WR SERIES.pdf; Lifecycle: Comp-Approve; MATERIAL: CHIP; Manuf_PN: RR0510X-000-XN; Manuf_name: CYNTEC CO.. LTD.; Manuftr: CYN; Part_Type: *LF_Resistor; Status: Preferred; TOLERANCE: 5%; TOP_BOT: TOP; WATTAGE: 1/16W; fp_ECN: 0402 SERIES_LL34.xls
R2 R360 R786 R789 R924 R925 = R: RES CHIP 4.7K 1/16W +-5% (0402); CLASS: DISCRETE; CMPLS_LVL: EP; Data: WTC_LF_WR SERIES.pdf; Lifecycle: Comp-Approve; MATERIAL: CHIP; Manuf_PN: RR0510S-472-JN; Manuf_name: CYNTEC CO.. LTD.; Manuftr: CYN; Part_Type: *LF_Resistor; Status: Preferred; TOLERANCE: 5%; TOP_BOT: TOP; WATTAGE: 1/16W; fp_ECN: 0402 SERIES_LL34.xls
R10 R11 R880 = R: RES CHIP 4.7K 1/16W +-5% (0402); CLASS: DISCRETE; CMPLS_LVL: EP; Data: WTC_LF_WR SERIES.pdf; Lifecycle: Comp-Approve; MATERIAL: CHIP; Manuf_PN: RR0510S-472-JN; Manuf_name: CYNTEC CO.. LTD.; Manuftr: CYN; Not_insert: NI; Part_Type: *LF_Resistor; Status: Preferred; TOLERANCE: 5%; TOP_BOT: BOT; WATTAGE: 1/16W; fp_ECN: 0402 SERIES_LL34.xls
R12 R930 = R: RES CHIP 220 1/16W +-5%(0402); CLASS: DISCRETE; CMPLS_LVL: EP; Data: WTC_LF_WR SERIES.pdf; Lifecycle: Comp-Approve; MATERIAL: CHIP; Manuf_PN: RR0510S-221-JN; Manuf_name: CYNTEC CO.. LTD.; Manufacturer: CYN; Manuftr: CYN; Not_insert: NI_F; Part_Type: *LF_Resistor; Standard: ##; Status: Preferred; TOLERANCE: 5%; WATTAGE: 1/16W; fp_ECN: 0402 SERIES_LL34.xls; top_bot: BOT
R13 R790 R791 R922 = R: RES CHIP 1K 1/16W 5%(0402); CLASS: DISCRETE; CMPLS_LVL: EP; Data: WTC_LF_WR SERIES.pdf; Lifecycle: Comp-Approve; MATERIAL: CHIP; Manuf_PN: RR0510S-102-JN; Manuf_name: CYNTEC CO.. LTD.; Manuftr: CYN; Part_Type: *LF_Resistor; Status: Normal; TOLERANCE: 5%; TOP_BOT: TOP; WATTAGE: 1/16W; fp_ECN: 0402 SERIES_LL34.xls
R357 = R: RES CHIP 1.69K 1/16W +-1%(0402); CLASS: DISCRETE; CMPLS_LVL: EP(V1); Data: RHT_LF_RES SERIES-2.pdf; From_pj: T2A-TONY; Lifecycle: Comp-Approve; MATERIAL: CHIP; Manuf_PN: CR021K69F002S; Manuf_name: RTECH TECHNOLOGY CO..LTD.(Compostar); Manuftr: RHT; Part_Type: *LF_Resistor; RD_CMPLS_LVL: EP(V1); TOLERANCE: 1%; TOP_BOT: BOT; WATTAGE: 1/16W; fp_ECN: 0402 SERIES_LL34.xls
R358 = R: RES CHIP 3.3K 1/16W +-1%(0402); CLASS: DISCRETE; CMPLS_LVL: EP; Data: TAI_LF_RM SERIES-2.pdf; From_pj: S75-LA; Lifecycle: Comp-Approve; MATERIAL: CHIP; Manuf_PN: RM04FTN3301; Manuf_name: TA-I TECHNOLOGY CO..LTD.; Manuftr: TAI; Part_Type: *LF_Resistor; Standard: ##; Status: Preferred; TOLERANCE: 1%; TOP_BOT: BOT; WATTAGE: 1/16W; fp_ECN: 0402 SERIES_LL34.xls
R359 R730 R875 = R: RES CHIP 4.7K 1/16W +-5% (0402); CLASS: DISCRETE; CMPLS_LVL: EP; Data: WTC_LF_WR SERIES.pdf; Lifecycle: Comp-Approve; MATERIAL: CHIP; Manuf_PN: RR0510S-472-JN; Manuf_name: CYNTEC CO.. LTD.; Manuftr: CYN; Part_Type: *LF_Resistor; Status: Preferred; TOLERANCE: 5%; TOP_BOT: BOT; WATTAGE: 1/16W; fp_ECN: 0402 SERIES_LL34.xls
R732 R787 R788 = R: RES CHIP 4.7K 1/16W +-5% (0402); CLASS: DISCRETE; CMPLS_LVL: EP; Data: WTC_LF_WR SERIES.pdf; Lifecycle: Comp-Approve; MATERIAL: CHIP; Manuf_PN: RR0510S-472-JN; Manuf_name: CYNTEC CO.. LTD.; Manuftr: CYN; Not_insert: NI; Part_Type: *LF_Resistor; Status: Preferred; TOLERANCE: 5%; TOP_BOT: TOP; WATTAGE: 1/16W; fp_ECN: 0402 SERIES_LL34.xls
R792 R920 = R: RES CHIP 1K 1/16W 5%(0402); CLASS: DISCRETE; CMPLS_LVL: EP; Data: WTC_LF_WR SERIES.pdf; Lifecycle: Comp-Approve; MATERIAL: CHIP; Manuf_PN: RR0510S-102-JN; Manuf_name: CYNTEC CO.. LTD.; Manuftr: CYN; Not_insert: NI; Part_Type: *LF_Resistor; Status: Normal; TOLERANCE: 5%; TOP_BOT: TOP; WATTAGE: 1/16W; fp_ECN: 0402 SERIES_LL34.xls
R900 R923 = R: RES CHIP 10K 1/16W +-1% (0402); CLASS: DISCRETE; CMPLS_LVL: EP; Data: WTC_LF_WR SERIES.pdf; From_pj: S82; Lifecycle: Comp-Approve; MATERIAL: CHIP; Manuf_PN: RR0510S-103-FN; Manuf_name: CYNTEC CO.. LTD.; Manuftr: CYN; Not_insert: NI; Part_Type: *LF_Resistor; Status: Preferred; TOLERANCE: 1%; TOP_BOT: TOP; WATTAGE: 1/16W; fp_ECN: 0402 SERIES_LL34.xls
R901 R921 = R: RES CHIP 10K 1/16W +-1% (0402); CLASS: DISCRETE; CMPLS_LVL: EP; Data: WTC_LF_WR SERIES.pdf; From_pj: S82; Lifecycle: Comp-Approve; MATERIAL: CHIP; Manuf_PN: RR0510S-103-FN; Manuf_name: CYNTEC CO.. LTD.; Manuftr: CYN; Part_Type: *LF_Resistor; Status: Preferred; TOLERANCE: 1%; TOP_BOT: TOP; WATTAGE: 1/16W; fp_ECN: 0402 SERIES_LL34.xls
R44 R926 R927 = R: RESISTOR CHIP 0 1/16W +-5%(0402); CLASS: DISCRETE; CMPLS_LVL: EP; Data: WTC_LF_WR SERIES.pdf; Lifecycle: Comp-Approve; MATERIAL: CHIP; Manuf_PN: RR0510X-000-XN; Manuf_name: CYNTEC CO.. LTD.; Manuftr: CYN; Not_insert: NI_F; Part_Type: *LF_Resistor; Status: Preferred; TOLERANCE: 5%; TOP_BOT: TOP; WATTAGE: 1/16W; fp_ECN: 0402 SERIES_LL34.xls
U5 = FT232RLREEL: IC OTHER (28P)FT232RL-REEL(SSOP); CLASS: IC; Data: FTI_FT232RL-REEL.pdf; From_pj: F06-RAYMOND; Lifecycle: P/N Release; MATERIAL: IC; Manuf_name: Future Technology Devices International Limited .; Manuftr: FTI; Part_Type: *LF_Chipset; RD_CMPLS_LVL: EP(V1); TOP_BOT: BOT
U10 = MODULE_RN42IRM: BLUETOOTH MODULE RN42-I/RM; CLASS: IO; Data: MRP_RN-42(N).pdf; From_pj: F03R-WENLUNG; Lifecycle: Comp-Release Qty; MATERIAL: MOD; Manuf_PN: RN42-I/RM; Manuf_name: MICROCHIP TECHNOLOGY INC.; Manuftr: MRP; Part_Type: *LF_modules; RD_CMPLS_LVL: EU(V1); Standard: Non-Preferred; TOP_BOT: BOT
U15 = SCONN9_2UP1000000111F: CONN SMD USB3.0 9P 1R FR(P1.0,H1.85); CLASS: IO; Data: SIT_2UP1000-000111F.pdf; From_pj: F06-SHERRY; Lifecycle: P/N Release; MATERIAL: IO; Manuf_PN: 2UP1000-000111F; Manuf_name: SINGATRON ENTERPRISE CO., LTD. (SINGATRON ELECTRONIC(CHINA) CO., LTD.); Manuftr: SIT; Part_Type: *LF_Connector; RD_CMPLS_LVL: EP(V1); TOP_BOT: BOT
U16 = M24128: IC(8P) EEPROM M24128-BWMN6TP(SO8); CLASS: IC; CMPLS_LVL: EP; Data: SGT_M24256-B_M24128-B.pdf; From_pj: S2D-TERRY; Lifecycle: Comp-Approve; MATERIAL: IC; Manuf_name: SGS-THOMSON(STMicroelectronics); Manuftr: SGT; Part_Type: *LF_Chipset; TOP_BOT: TOP
C244 = CAP_NP: CAP CHIP 0.1U 16V(10%,X7R,0402); CLASS: DISCRETE; CMPLS_LVL: EP; Data: MUR_LF_CAP SERIES_1.pdf; From_pj: S10-ANTONY; MATERIAL: X7R; Manuf_PN: GRM155R71C104K; Manuf_name: MURATA ERIE N.A. INC TAIWAN BRANCH Okayama Murata Mfg.Co.,Ltd. Wakura Murata Mfg; Manufacturer: MUR; Part_Type: *LF_C0402; Status: Preferred; TOLERANCE: 10%; TOP_BOT: TOP; VOLTAGE: 16V
D6 = LED20S_LTD3813CKDP: LED MODULE SMD(20P)RED(LTD-3813CKD-P); CLASS: IC; Data: LIT_LTD-3813CKD-P.pdf; From_pj: F06-RAYMOND; Lifecycle: Comp-Release Qty; MATERIAL: IC; Manuf_PN: LTD-3813CKD-P; Manuf_name: LITEON ELECTRONIC CO., LTD.; Manuftr: LIT; Part_Type: *LF_Semiconductor; RD_CMPLS_LVL: EU(V1); TOP_BOT: TOP
R76 R724 R911 = R: RES CHIP 2.7K 1/16W +-5%(0402); CLASS: DISCRETE; CMPLS_LVL: EP; Data: TAI_LF_RM SERIES.pdf; Lifecycle: Comp-Approve; MATERIAL: CHIP; Manuf_PN: RR0510S-272-JN; Manuf_name: CYNTEC CO.. LTD.; Manuftr: CYN; Part_Type: *LF_Resistor; Standard: ##; Status: Preferred; TOLERANCE: 5%; TOP_BOT: BOT; WATTAGE: 1/16W; fp_ECN: 0402 SERIES_LL34.xls
R78 = R: RES CHIP 200 1/16W +-1%(0402); CLASS: DISCRETE; Data: TR-0306029.pdf; From_pj: S06; MATERIAL: CHIP; Manuf_PN: RC0402FR-07200R; Manuf_name: YAGEO CORPORATION; Manuftr: YGO; Part_Type: Resistor; Status: Normal; TOLERANCE: 1%; TOP_BOT: BOT; WATTAGE: 1/16W; fp_ECN: 0402 SERIES_LL34.xls
R725 = R: RES CHIP 200 1/16W +-1%(0402); CLASS: DISCRETE; Data: TR-0306029.pdf; From_pj: S06; MATERIAL: CHIP; Manuf_PN: RC0402FR-07200R; Manuf_name: YAGEO CORPORATION; Manuftr: YGO; Part_Type: Resistor; Status: Normal; TOLERANCE: 1%; TOP_BOT: TOP; WATTAGE: 1/16W; fp_ECN: 0402 SERIES_LL34.xls
R758 R759 = R: RES CHIP 300 1/16W +-1%(0402); CLASS: DISCRETE; CMPLS_LVL: EP; Data: WTC_LF_WR SERIES-4.pdf; From_pj: TU1-YIMIN; Lifecycle: Comp-Approve; MATERIAL: CHIP; Manuf_PN: WR04X3000FTL; Manuf_name: WALSIN TECHNOLOGY CORPORATION; Manufacturer: CYN; Manuftr: WTC; Part_Type: *LF_Resistor; Standard: End of Design; TOLERANCE: 1%; WATTAGE: 1/16W; fp_ECN: 0402 SERIES_LL34.xls; top_bot: TOP
R910 R915 R918 R944 = R: RES CHIP 49.9K 1/16W +-1%(0402); CLASS: DISCRETE; CMPLS_LVL: EP; Data: WTC_LF_WR SERIES-4.pdf; From_pj: LU1-EASON; Lifecycle: Comp-Approve; MATERIAL: CHIP; Manuf_PN: WR04X4992FTL; Manuf_name: WALSIN TECHNOLOGY CORPORATION; Manuftr: WTC; Part_Type: *LF_Resistor; Standard: ##; TOLERANCE: 1%; TOP_BOT: TOP; WATTAGE: 1/16W; fp_ECN: 0402 SERIES_LL34.xls
S1 = SW_PUSHBUTTON4P_24: SWITCH SMD TACT(DTSM-65R-Q-T/R); CLASS: IO; Data: DIP_DTSM-65R-Q-TR.pdf; From_pj: S2VD-VINCENT; Lifecycle: Comp-Approve; MATERIAL: MECH; Manuf_PN: DTSM-65R-Q-T/R; Manuf_name: Diptronics Manufacturing Inc.; Manuftr: DIP; Part_Type: *LF_Mech; RD_CMPLS_LVL: EP(V1); TOP_BOT: TOP
S2 = SW_PUSHBUTTON4P_1-3: SWITCH SMD TACT 4P(DTSM-65K-Q-T/R); CLASS: IO; Data: DIP_DTSM-65K-Q-TR_REVA.pdf; From_pj: S2P-SEAN; Lifecycle: Comp-Approve; MATERIAL: MECH; Manuf_PN: DTSM-65K-Q-T/R; Manuf_name: Diptronics Manufacturing Inc.; Manuftr: DIP; Part_Type: *LF_Mech; RD_CMPLS_LVL: EU(V1); TOP_BOT: TOP
BT1 = SCONN2_502730020N001: CONN SMD HEADER 2P 1R MS(P1.25,H4.8); CLASS: IO; Data: HRS_DF13C-2P-1.25V21.pdf; From_pj: F08-RAYMOND; Lifecycle: Comp-Release Qty; MATERIAL: IO; Manuf_PN: DF13C-2P-1.25V(21); Manuf_name: HIROSE ELECTRIC; Manuftr: HRS; Part_Type: *LF_Connector; RD_CMPLS_LVL: EP(V1); TOP_BOT: BOT
C290-C298 = CAP_NP: CAP CHIP 1UF 25V(+-10%,X6S,0402); CLASS: DISCRETE; CMPLS_LVL: EP(V1); Data: MUR_GRM155R72A221KA01-01.pdf; From_pj: F06-RAYMOND; Lifecycle: Comp-Approve; MATERIAL: X6S; Manuf_PN: GRM155C81E105K; Manuf_name: MURATA ERIE N.A. INC TAIWAN BRANCH Okayama Murata Mfg.Co.,; Manuftr: MUR; Part_Type: *LF_C0402; RD_CMPLS_LVL: EP(V1); TOLERANCE: 10%; TOP_BOT: TOP; VOLTAGE: 25V; fp_ECN: 0402 SERIES_LL34.xls
C299 = CAP_NP: CAP CHIP 0.1U 25V(+-10%,X7R,0402); CLASS: DISCRETE; Data: YGO_CA-CC-SC SERIES.pdf; From_pj: F03-KC; Lifecycle: Comp-Approve; MATERIAL: X7R; Manuf_PN: CC0402KRX7R8BB104; Manuf_name: YAGEO CORPORATION; Manuftr: YGO; Part_Type: *LF_C0402; RD_CMPLS_LVL: EP(V1); TOLERANCE: 10%; TOP_BOT: TOP; VOLTAGE: 25V; fp_ECN: 0402 SERIES_LL34.xls
C300 C336 = CAP_NP: CAP CHIP 0.1U 16V(10%.X7R.0402); CLASS: DISCRETE; CMPLS_LVL: EP(V1); Data: MUR_LF_CAP SERIES_1.pdf; FPLIST: C0402,C0402_OCTAGONXA; From_pj: S5A-TRAVIS; Lifecycle: Comp-Approve; MATERIAL: X7R; Manuf_PN: WBM155R71C104K; Manuf_name: MURATA ERIE N.A. INC TAIWAN BRANCH Okayama Murata Mfg.Co..Ltd. Wakura Murata Mfg; Manuftr: MUR; Part_Type: *LF_C0402; RD_CMPLS_LVL: EP(V1); TOLERANCE: 10%; TOP_BOT: TOP; VOLTAGE: 16V; fp_ECN: 0402 SERIES_LL34.xls
J4 = SCONN30_5050103001001: CONN SMD FFC 30P 1R FR(P0.5,H2.0); CLASS: IO; CMPLS_LVL: EP(V1); Data: ACS_50501-XXXXX-XXX_REVK.pdf; From_pj: S2P-OZ; Lifecycle: Comp-Approve; MATERIAL: IO; Manuf_PN: 50501-03001-001; Manuf_name: ACES ELECTRONIC CO., LTD.; Manuftr: ACS; Part_Type: *LF_Connector; RD_CMPLS_LVL: EP(V1); TOP_BOT: BOT
J5 = SCONN2_502730020N001: CONN SMD HEADER 2P 1R MS(P1.25); CLASS: IO; Data: ACS_50273-0020N-V09.pdf; From_pj: F08-SHERRY; Lifecycle: Comp-Release Qty; MATERIAL: IO; Manuf_PN: 50273-0020N-V09; Manuf_name: ACES ELECTRONIC CO., LTD.; Manuftr: ACS; Part_Type: *LF_Connector; RD_CMPLS_LVL: EP(V1); TOP_BOT: BOT
Q29 Q30 = MOSFET_N_GSD: TRANS MOS CSD17484F4(30V,3A,0.5W); CLASS: IC; Data: TIC_CSD17484F4.pdf; ESD_CDM: NA; ESD_HBM: NA; ESD_MM: NA; From_pj: F08-TOM; Lifecycle: P/N Release; MATERIAL: IC; MSD: NA; Manuf_name: TEXAS INSTRUMENTS SUPPLY CO.,; Manuftr: TIC; PIN_LENGTH_LONG_PIN: 0 MILS; PIN_LENGTH_SHORT_PIN: 0 MILS; Part_Type: *LF_Semiconductor; RD_CMPLS_LVL: EP(V1); Standard: Potential; TOP_BOT: TOP
R512 R757 = R: RES CHIP 220 1/16W +-5%(0402); CLASS: DISCRETE; CMPLS_LVL: EP; Data: WTC_LF_WR SERIES.pdf; Lifecycle: Comp-Approve; MATERIAL: CHIP; Manuf_PN: RR0510S-221-JN; Manuf_name: CYNTEC CO.. LTD.; Manufacturer: CYN; Manuftr: CYN; Not_insert: NI_F; Part_Type: *LF_Resistor; Standard: ##; Status: Preferred; TOLERANCE: 5%; WATTAGE: 1/16W; fp_ECN: 0402 SERIES_LL34.xls; top_bot: TOP
R941 = R: RES CHIP 330 1/16W +-1%(0402); CLASS: DISCRETE; CMPLS_LVL: EP; Data: TAI_LF_RM SERIES-2.pdf; From_pj: S75-LA; Lifecycle: Comp-Approve; MATERIAL: CHIP; Manuf_PN: RM04FTN3300; Manuf_name: TA-I TECHNOLOGY CO..LTD.; Manufacturer: CYN; Manuftr: TAI; Part_Type: *LF_Resistor; Standard: End of Design; Status: Preferred; TOLERANCE: 1%; WATTAGE: 1/16W; fp_ECN: 0402 SERIES_LL34.xls; top_bot: TOP
R942 = R: RES CHIP 2.2K 1/16W +-1%(0402); CLASS: DISCRETE; CMPLS_LVL: EP; Data: TAI_LF_RM SERIES-3.pdf; From_pj: T96-KC; Lifecycle: Comp-Approve; MATERIAL: CHIP; Manuf_PN: RM04FTN2201; Manuf_name: TA-I TECHNOLOGY CO..LTD.; Manufacturer: CYN; Manuftr: TAI; Part_Type: *LF_Resistor; Standard: End of Design; TOLERANCE: 1%; WATTAGE: 1/16W; fp_ECN: 0402 SERIES_LL34.xls; top_bot: TOP
R943 = R: RESISTOR CHIP 0 1/16W +-5%(0402); CLASS: DISCRETE; CMPLS_LVL: EP; Data: WTC_LF_WR SERIES.pdf; Lifecycle: Comp-Approve; MATERIAL: CHIP; Manuf_PN: RR0510X-000-XN; Manuf_name: CYNTEC CO.. LTD.; Manuftr: CYN; Not_insert: NI; Part_Type: *LF_Resistor; Status: Preferred; TOLERANCE: 5%; TOP_BOT: BOT; WATTAGE: 1/16W; fp_ECN: 0402 SERIES_LL34.xls
U24 = BQ29700DSER: IC OTHER(6P)BQ29700DSER(WSON); CLASS: IC; Data: TIC_BQ29700DSER.pdf; ESD_CDM: NA; ESD_HBM: NA; ESD_MM: NA; From_pj: F08-TOM; Lifecycle: P/N Release; MATERIAL: IC; MSD: NA; Manuf_name: TEXAS INSTRUMENTS SUPPLY CO.,; Manuftr: TIC; PIN_LENGTH_LONG_PIN: 0 MILS; PIN_LENGTH_SHORT_PIN: 0 MILS; Part_Type: *LF_Chipset; RD_CMPLS_LVL: EP(V1); Standard: Potential; TOP_BOT: TOP
DM8 DM9 = DUMMY_SYMBOL: CLASS: IO; MATERIAL: MECH; Not_insert: NI; Part_Type: Mech; TOP_BOT: TOP
H2-H5 = HOLE_N: CLASS: IO; DIP_SMD: DIP; From_pj: S3E-DEREK; MATERIAL: MECH; Not_insert: NI; Part_Type: Mech; TOP_BOT: TOP
TP7 = TP: TP12_BOM ONLY; CLASS: IO; DIP_SMD: DIP; From_pj: TU1B-MARTIN; MATERIAL: MISC; Part_Type: Misc; TOP_BOT: TOP
C273 C278 C316 C318-C322 C333 = CAP_NP: CAP CHIP 0.1U 16V(10%.X7R.0402); CLASS: DISCRETE; CMPLS_LVL: EP; Data: MUR_LF_CAP SERIES_1.pdf; From_pj: S10-ANTONY; Lifecycle: Comp-Approve; MATERIAL: X7R; Manuf_PN: GRM155R71C104K; Manuf_name: MURATA ERIE N.A. INC TAIWAN BRANCH Okayama Murata Mfg.Co..Ltd. Wakura Murata Mfg; Manuftr: MUR; Not_insert: NI_F; Part_Type: *LF_C0402; Standard: ##; Status: Preferred; TOLERANCE: 10%; TOP_BOT: BOT; VOLTAGE: 16V; fp_ECN: 0402 SERIES_LL34.xls
CN1 = SCONN5_1051330011: CONN SMD MICRO USB 5P 1R FS(P0.65,H6.7); CLASS: IO; CMPLS_LVL: EP(V1); Data: MLX_SD-105133-011_REVB.pdf; From_pj: F06-RAYMOND; Lifecycle: Comp-Approve; MATERIAL: IO; Manuf_PN: 105133-0011; Manuf_name: MOLEX TAIWAN LTD.DONGGUAN MOLEX INTERCONNECT CO., LTD; Manuftr: MLX; Not_insert: NI; Part_Type: *LF_Connector; RD_CMPLS_LVL: EP(V1); TOP_BOT: BOT
D13 = LED_0: LED SMD(2P) GREEN(LTST-C281PGKT-Q); CLASS: IC; CMPLS_LVL: EP(V1); Data: LIT_LTST-C281PGKT-Q.pdf; From_pj: MF1-TONY; Lifecycle: Comp-Approve; MATERIAL: IC; Manuf_PN: LTST-C281PGKT-Q; Manuf_name: LITEON ELECTRONIC CO., LTD.; Manuftr: LIT; Not_insert: NI_F; Part_Type: *LF_Semiconductor; RD_CMPLS_LVL: EP(V1); TOP_BOT: TOP; fp_ECN: BEGR0296Z01.msg
D15 = LED_0: LED SMD(2P) RED(19-213SURC/S530-A3/TR8); CLASS: IC; CMPLS_LVL: EP; Data: 19-213SURC-S530-XX-TR8.pdf; From_pj: YE7-DAVID; Lifecycle: Comp-Approve; MATERIAL: IC; Manuf_PN: 19-213SURC/S530-A3/TR8; Manuf_name: EVERLIGHT; Manuftr: EVL; Part_Type: *LF_Semiconductor; Standard: End of Design; TOP_BOT: TOP
J13 = SCONN4_502280047N001: CONN SMD WAFER,4P,1R,MS(P1.0,H4.3); CLASS: IO; CMPLS_LVL: EP(V1); Data: ACS_50228-XXXXX-XXX_REVJ.pdf; From_pj: F07-HENRY; Lifecycle: Comp-Approve; MATERIAL: IO; Manuf_PN: 50228-0047N-001; Manuf_name: ACES ELECTRONIC CO., LTD.; Manuftr: ACS; Not_insert: NI_F; Part_Type: *LF_Connector; RD_CMPLS_LVL: EP(V1); TOP_BOT: BOT
R54 R873 = R: RESISTOR CHIP 0 1/16W +-5%(0402); BOM: AST2300; CLASS: DISCRETE; CMPLS_LVL: EP; Data: WTC_LF_WR SERIES.pdf; Lifecycle: Comp-Approve; MATERIAL: CHIP; Manuf_PN: RR0510X-000-XN; Manuf_name: CYNTEC CO.. LTD.; Manufacturer: CYN; Manuftr: CYN; Not_insert: NI; Part_Type: *LF_Resistor; Status: Preferred; TOLERANCE: 5%; TOP_BOT: BOT; WATTAGE: 1/16W; fp_ECN: 0402 SERIES_LL34.xls
R72 R469 R473 R474 R881 = R: RESISTOR CHIP 0 1/16W +-5%(0402); CLASS: DISCRETE; CMPLS_LVL: EP; Data: WTC_LF_WR SERIES.pdf; Lifecycle: Comp-Approve; MATERIAL: CHIP; Manuf_PN: RR0510X-000-XN; Manuf_name: CYNTEC CO.. LTD.; Manuftr: CYN; Not_insert: NI_F; Part_Type: *LF_Resistor; Status: Preferred; TOLERANCE: 5%; TOP_BOT: BOT; WATTAGE: 1/16W; fp_ECN: 0402 SERIES_LL34.xls
R79 R513 R516 = R: RES CHIP 33.2 1/16W +-1%(0402); CLASS: DISCRETE; CMPLS_LVL: EP; Data: CYN_LF_RL SERIES.pdf; From_pj: A06-EDISON; Lifecycle: Comp-Approve; MATERIAL: CHIP; Manuf_PN: RR0510S-33R2-FN; Manuf_name: CYNTEC CO.. LTD.; Manuftr: CYN; Not_insert: NI_F; Part_Type: *LF_Resistor; TOLERANCE: 1%; TOP_BOT: BOT; WATTAGE: 1/16W; fp_ECN: 0402 SERIES_LL34.xls
R471 R475 R882 = R: RES CHIP 10K 1/16W +-1% (0402); CLASS: DISCRETE; CMPLS_LVL: EP; Data: WTC_LF_WR SERIES.pdf; From_pj: S82; Lifecycle: Comp-Approve; MATERIAL: CHIP; Manuf_PN: RR0510S-103-FN; Manuf_name: CYNTEC CO.. LTD.; Manuftr: CYN; Not_insert: NI_F; Part_Type: *LF_Resistor; Status: Preferred; TOLERANCE: 1%; TOP_BOT: BOT; WATTAGE: 1/16W; fp_ECN: 0402 SERIES_LL34.xls
R870 R871 = R: RESISTOR CHIP 0 1/16W +-5%(0402); BOM: AST2300; CLASS: DISCRETE; CMPLS_LVL: EP; Data: WTC_LF_WR SERIES.pdf; Lifecycle: Comp-Approve; MATERIAL: CHIP; Manuf_PN: RR0510X-000-XN; Manuf_name: CYNTEC CO.. LTD.; Manufacturer: CYN; Manuftr: CYN; Not_insert: NI_F; Part_Type: *LF_Resistor; Status: Preferred; TOLERANCE: 5%; TOP_BOT: TOP; WATTAGE: 1/16W; fp_ECN: 0402 SERIES_LL34.xls
R888 = R: RESISTOR CHIP 0 1/16W +-5%(0402); CLASS: DISCRETE; CMPLS_LVL: EP; Data: WTC_LF_WR SERIES.pdf; Lifecycle: Comp-Approve; MATERIAL: CHIP; Manuf_PN: RR0510X-000-XN; Manuf_name: CYNTEC CO.. LTD.; Manuftr: CYN; Part_Type: *LF_Resistor; Status: Preferred; TOLERANCE: 5%; TOP_BOT: BOT; WATTAGE: 1/16W; fp_ECN: 0402 SERIES_LL34.xls
R912 R914 R916 R917 = R: RES CHIP 49.9K 1/16W +-1%(0402); CLASS: DISCRETE; CMPLS_LVL: EP; Data: WTC_LF_WR SERIES-4.pdf; From_pj: LU1-EASON; Lifecycle: Comp-Approve; MATERIAL: CHIP; Manuf_PN: WR04X4992FTL; Manuf_name: WALSIN TECHNOLOGY CORPORATION; Manuftr: WTC; Part_Type: *LF_Resistor; Standard: ##; TOLERANCE: 1%; TOP_BOT: BOT; WATTAGE: 1/16W; fp_ECN: 0402 SERIES_LL34.xls
R913 = R: RES CHIP 0 1/16W +-5%(0402)EF; CLASS: DISCRETE; CMPLS_LVL: EP(V1); From_pj: S6E-KENHU; Lifecycle: Comp-Approve; MATERIAL: CHIP; Manuf_PN: WR04X000PTR; Manuf_name: WALSIN TECHNOLOGY CORPORATION; Manuftr: WTC; Not_insert: NI; Part_Type: *LF_Resistor; RD_CMPLS_LVL: EP(V1); Standard: End of Design; TOLERANCE: 5%; TOP_BOT: BOT; WATTAGE: 1/16W; fp_ECN: 0402 SERIES_LL34.xls
R919 = R: RES CHIP 2.7K 1/16W +-5%(0402); CLASS: DISCRETE; CMPLS_LVL: EP; Data: TAI_LF_RM SERIES.pdf; Lifecycle: Comp-Approve; MATERIAL: CHIP; Manuf_PN: RR0510S-272-JN; Manuf_name: CYNTEC CO.. LTD.; Manuftr: CYN; Part_Type: *LF_Resistor; Standard: ##; Status: Preferred; TOLERANCE: 5%; TOP_BOT: TOP; WATTAGE: 1/16W; fp_ECN: 0402 SERIES_LL34.xls
R928 = R: RES CHIP 41.2K 1/16W +-1%(0402); CLASS: DISCRETE; CMPLS_LVL: EP(V1); Data: TAI_RM04FTN4122.pdf; From_pj: UH3M-KEVIN; Lifecycle: Comp-Approve; MATERIAL: CHIP; Manuf_PN: RM04FTN4122; Manuf_name: TA-I TECHNOLOGY CO.,LTD.; Manuftr: TAI; Part_Type: *LF_Resistor; RD_CMPLS_LVL: EP(V1); TOLERANCE: 1%; TOP_BOT: BOT; WATTAGE: 1/16W; fp_ECN: 0402 SERIES_LL34.xls
R929 = R: RES CHIP 8.25K 1/16W +-1% (0402); CLASS: DISCRETE; CMPLS_LVL: EP; Data: YGO_RC0402 SERIES.pdf; From_pj: RS2-MATT; MATERIAL: CHIP; Manuf_PN: RC0402FR-078K25; Manuf_name: YAGEO CORPORATION; Manuftr: YGO; Part_Type: *LF_Resistor; TOLERANCE: 1%; TOP_BOT: BOT; WATTAGE: 1/16W; fp_ECN: 0402 SERIES_LL34.xls
SW5 = SW_PUSHBUTTON4P_24: SWITCH PUSH BUTTON DTSM-65N-S-Q-T/R H9.5; CLASS: IO; Data: DIP_DTSM-65N-S-Q-TR.pdf; From_pj: JB8-STANLEY; Lifecycle: Comp-Approve; MATERIAL: MECH; Manuf_PN: DTSM-65N-S-Q-T/R; Manuf_name: Diptronics Manufacturing Inc.; Part_Type: *LF_Mech; RD_CMPLS_LVL: EP(V1); Standard: ##; TOP_BOT: TOP
SW6 = SW6S_HSS177: SWITCH SMD TACT(HSS177); CLASS: IO; Data: TKS_HSS177.pdf; From_pj: F06-RAYMOND; MATERIAL: MECH; Manuf_PN: HSS177; Manuf_name: TOKAI SANGYO CO..LTD; Manuftr: TKS; Part_Type: Tmp; TOP_BOT: TOP
C65 = CAP_NP: CAP CHIP 0.1U 10V(+-10%.X7R.0402); CLASS: DISCRETE; CMPLS_LVL: EP; Data: RHT_LF_CAP SERIES-1.pdf; From_pj: S82-ICE; Lifecycle: Comp-Approve; MATERIAL: X7R; Manuf_PN: GRM155R71A104K; Manuf_name: "MURATA ERIE N.A. INC TAIWAN BRANCH Okayama Murata Mfg.Co..Ltd.Wakura Murata Mfg; Manuftr: MUR; Not_insert: NI_F; Part_Type: *LF_C0402; Standard: ##; Status: Preferred; TOLERANCE: 10%; TOP_BOT: TOP; VOLTAGE: 10V; fp_ECN: 0402 SERIES_LL34.xls
C258 C272 C276 C317 = CAP_NP: CAP CHIP 0.01U 50V(+-10%,X7R,0402); CLASS: DISCRETE; CMPLS_LVL: EP(V1); Data: MUR_MLCC_20110826.pdf; From_pj: T2B-CHEESE; Lifecycle: Comp-Approve; MATERIAL: X7R; Manuf_PN: WBM155R71H103K; Manuf_name: MURATA ERIE N.A. INC TAIWAN BRANCH Okayama Murata Mfg.Co.,Ltd.; Manuftr: MUR; Not_insert: NI_F; Part_Type: *LF_C0402; RD_CMPLS_LVL: EP(V1); TOLERANCE: 10%; TOP_BOT: BOT; VOLTAGE: 50V; fp_ECN: 0402 SERIES_LL34.xls
C259 C275 C279 C280 C315 = CAP_NP: CAP CHIP 1U.6.3V(+-10%.X7R.0402); CLASS: DISCRETE; CMPLS_LVL: EP; Data: MKP_LF_CAP SERIES.pdf; From_pj: T94-JEFF; Lifecycle: Comp-Approve; MATERIAL: X7R; Manuf_PN: MAG02X7R0J105K; Manuf_name: Matsuki Precision Ceramic Co.. Ltd.Matsuki Polymer Technology Co.. Ltd.; Manuftr: MKP; Not_insert: NI_F; Part_Type: *LF_C0402; TOLERANCE: 10%; TOP_BOT: BOT; VOLTAGE: 6.3V; fp_ECN: 0402 SERIES_LL34.xls
C323 = CAP_NP: CAP CHIP 2.2UF 6.3V(+-10%.X7R.0603); CLASS: DISCRETE; CMPLS_LVL: EP; Data: SAM_MLCC.pdf; From_pj: S99Q-JACK; Lifecycle: Comp-Approve; MATERIAL: X7R; Manuf_PN: CL10B225KQ8NNNC; Manuf_name: SAMSUNG ELECTRONICS CO..LTD SAMSUNG SDI CO..LTD; Manuftr: SAM; Not_insert: NI_F; Part_Type: *LF_C0603; TOLERANCE: 10%; TOP_BOT: BOT; VOLTAGE: 6.3V
OSC1 = OSC-4: OSC SMD 25MHZ(+-25PPM,3.3V)FJ2500009; CLASS: IO; Data: ERC_FJ2500009.pdf; From_pj: S2X-DAN; Lifecycle: Comp-Approve; MATERIAL: MISC; Manuf_PN: FJ2500009; Manuf_name: ECERA COMTEK CORPORATION (Pericom SaRonix Ecera Technology Corporation) P.S.E; Manuftr: ERC; Part_Type: *LF_Misc; RD_CMPLS_LVL: EP(V1); Standard: Non-Preferred; TOP_BOT: TOP
R51 = R: RES CHIP 10K 1/16W +-1% (0402); CLASS: DISCRETE; CMPLS_LVL: EP; Data: WTC_LF_WR SERIES.pdf; From_pj: S82; Lifecycle: Comp-Approve; MATERIAL: CHIP; Manuf_PN: RR0510S-103-FN; Manuf_name: CYNTEC CO.. LTD.; Manuftr: CYN; Not_insert: NI_F; Part_Type: *LF_Resistor; Status: Preferred; TOLERANCE: 1%; TOP_BOT: TOP; WATTAGE: 1/16W; fp_ECN: 0402 SERIES_LL34.xls
U21 = TM4C1290NCZADI3R: IC CTRL(212P)TM4C1290NCZADI3R(NFBGA); CLASS: IC; Data: TIC_TM4C1290NCZADI3R.pdf; From_pj: F08-RAYMOND; Lifecycle: P/N Release; MATERIAL: IC; Manuf_name: TEXAS INSTRUMENTS SUPPLY CO.,; Manuftr: TIC; Part_Type: *LF_Chipset; RD_CMPLS_LVL: EP(V1); Standard: Potential

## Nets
GND: BT1.G1 BT1.G2 C4.1 C21.1 C65.2 C241.1 C242.1 C243.1 C244.1 C252.2 C258.2 C259.2 C272.2 C273.2 C275.2 C276.2 C278.2 C279.2 C280.2 C289.2 C290.2 C291.2 C292.2 C293.2 C294.2 C298.2 C299.2 C300.2 C315.2 C316.2 C317.2 C318.2 C319.2 C320.2 C321.2 C322.2 C323.2 C332.1 C333.2 CN1.4(ID) CN1.5(GND) CN1.G1 CN1.G2 CN1.G3 J1.4(GND) J1.G1 J1.G2 J1.G3 J1.G4 J2.5(GND1) J2.G1(GND2) J2.G2(GND3) J2.G3(GND4) J2.G4(GND5) J2.G5(GND6) J2.G6(GND7) J4.13 J4.28 J4.G1 J4.G2 J5.1 J5.G1 J5.G2 J13.G1 J13.G2 OSC1.2(GND) Q30.S(SOURCE) R358.2 R789.2 R790.1 R791.1 R792.2 R900.1 R910.2 R912.2 R913.2 R914.2 R915.2 R916.2 R917.2 R918.2 R921.1 R923.1 R929.2 R942.1 R943.1 R944.2 SW6.G1 SW6.G2 SW6.G3 SW6.G4 U5.7(GND0) U5.18(GND1) U5.21(GND2) U5.25(AGND) U5.26(TEST) U10.1(GND1) U10.12(GND2) U10.28(GND3) U10.29(GND4) U10.G1 U10.G2 U10.G3 U10.G4 U15.4(GND) U15.G1 U15.G2 U16.4(VSS) U21.A1(GND) U21.A2(GND) U21.A18(GND) U21.A19(GND) U21.B1(GND) U21.B19(GND) U21.D18(GNDX2) U21.F10(GND) U21.G4(GNDA) U21.G5(VREFA-) U21.H10(GND) U21.H11(GND) U21.H12(GND) U21.J11(GND) U21.J12(GND) U21.K6(GND) U21.K9(GND) U21.K10(GND) U21.K13(GND) U21.K14(GND) U21.L8(GND) U21.L9(GND) U21.M8(GND) U21.M9(GND) U21.M10(GND) U21.N10(GND) U21.P16(GND) U21.R17(GND) U21.R18(GNDX) U21.V1(GND) U21.W1(GND) U21.W2(GND) ; also on sheet 13
P3V3_BIC: C65.1 C272.1 C273.1 C275.1 C276.1 C278.1 C279.1 C280.1 C289.1 C300.1 C315.1 C316.1 C317.1 C318.1 C319.1 C320.1 C321.1 D13.A J4.14 J4.15 J4.16 J4.23 J4.24 J4.25 J4.26 J4.27 OSC1.4(VDD) R51.1 R76.1 R471.2 R475.2 R724.1 R786.1 R787.1 R788.1 R875.1 R880.1 R882.2 R911.1 R919.1 R920.2 R922.2 R924.1 R925.1 U16.8(VCC) U21.F3(VDDA) U21.F4(VREFA+) U21.G10(VDD) U21.H9(VDD) U21.J8(VDD) U21.J9(VDD) U21.J10(VDD) U21.K7(VDD) U21.K8(VDD) U21.K11(VDD) U21.K12(VDD) U21.L10(VDD) U21.L11(VDD) U21.L12(VDD) U21.M11(VDD) U21.M12(VDD) U21.N16(VDD) U21.P10(VDD) U21.P17(VDD) ; also on sheet 13
P3V3_BT: C4.2 R2.1 R10.1 R11.1 R12.2 R730.1 R732.1 U10.11(VDD) ; also on sheet 13
P3V3_SW: R359.1 R360.1 ; also on sheet 13
P3V3_VOUT: C241.2 C242.2 U5.4(VCCIO) U5.17(3V3OUT)
P5V_MB: CN1.1(VBUS) FS2.2 R757.2 R758.2 R759.2 R901.2 U15.1(VBUS) ; also on sheet 13
P5V_MB_FUSE: FS2.1 J1.1(VBUS)
P5V_MB_LCD: J5.2 R757.1
P5V_USB: C243.2 J2.1(VBUS) R357.1 U5.19(RESET_N) U5.20(VCC) ; also on sheet 13
VBAT: BT1.1 R928.1 R930.2 R941.2 ; also on sheet 13
VBAT_CHG_BLINK: U21.U19(PK4)
VBAT_LOW_LED_N: D15.C ; also on sheet 13
VBAT_SCALED: C333.1 R928.2 R929.1 U21.B7(PE7_AIN21)
VDDC_OUTPUT: C258.1 C259.1 C322.1 C323.1 U21.E10(VDDC) U21.H16(VDDC)
BMC_HARTBEAT_LED_R: R512.1 U21.T13(PS5)
BMC_HEARTBEAT_LED: D13.C R512.2
BMC_RST_N: R875.2 U21.P18(RST#)
BMC_UART_R_RX: R54.2 U21.W3(PA1_U0TX)
BMC_UART_R_TX: R873.2 U21.V3(PA0_U0RX)
BMC_UART_RX: Q5.6(D1) R1.1 R54.1 R359.2 U15.9(SSTX+)
BMC_UART_RX_FT232: Q5.1(S1) U5.1(TXD)
BMC_UART_RX_R: R1.2 U10.14(UART_TX)
BMC_UART_TX: Q5.3(D2) R13.1 R873.1 U15.8(SSTX-)
BMC_UART_TX_FT232: Q5.4(S2) R360.2 U5.5(RXD)
BMC_UART_TX_R: R13.2 U10.13(UART_RX)
BQ25101_CHG_N: U21.V16(PK6) ; also on sheet 13
BT_STATUS_N: D3.C U10.21(GPIO5)
CELL_NEGATIVE: BT1.2 C336.2 Q29.S(SOURCE) R943.2 U24.4(VSS)
CHARGE_GATE: Q30.G(GATE) U24.2(COUT)
CLK_25M_MINIBMC_CLKIN: OSC1.3(OUT) R44.1
CLK_25M_MINIBMC_CLKIN_R: R44.2 U21.E19(OSC0)
DBCARD_INSERT_DET: U21.E7(PJ1)
DEBUG_V2_PRSNT: R900.2 R901.1 U15.7(GND_D)
DISCHARGE_GATE: Q29.G(GATE) U24.3(DOUT)
EEPROM_E0: R788.2 R790.2 U16.1(E0)
EEPROM_E1: R787.2 R791.2 U16.2(E1)
EEPROM_E2: R786.2 R792.1 U16.3(E2)
FACTORY_RST: R732.2 U10.22(GPIO4)
JTAG_TI_TCK: J13.1 R881.1 R882.1
JTAG_TI_TCK_R: R881.2 U21.B15(PC0_TCK_SWCLK)
JTAG_TI_TDI: J13.2 R474.1 R475.1
JTAG_TI_TDI_R: R474.2 U21.D14(PC2_TDI)
JTAG_TI_TDO: J13.3 R473.1
JTAG_TI_TDO_R: R473.2 U21.C14(PC3_TDO_SWO)
JTAG_TI_TMS: J13.4 R469.1 R471.1
JTAG_TI_TMS_R: R469.2 U21.C15(PC1_TMS_SWDIO)
LCD_C1M: C295.2 C297.2 J4.5
LCD_C1P: C297.1 J4.6
LCD_C2M: C296.2 J4.3
LCD_C2P: C296.1 J4.4
LCD_C3P: C295.1 J4.2
LCD_PAGE_SKP_DOWN: R915.1 SW6.6 U21.W10(PT0)
LCD_PAGE_SKP_ENTER: R916.1 SW6.2 U21.W6(PF2)
LCD_PAGE_SKP_LEFT: R914.1 SW6.3 U21.V7(PF4)
LCD_PAGE_SKP_PU: R919.2 SW6.5
LCD_PAGE_SKP_RIGHT: R918.1 SW6.4 U21.R10(PR7)
LCD_PAGE_SKP_UP: R917.1 SW6.1 U21.V4(PA4_SSI0XDAT0)
LCD_V0: C290.1 J4.7
LCD_V1: C292.1 J4.8
LCD_V2: C291.1 J4.9
LCD_V3: C293.1 J4.10
LCD_V4: C294.1 J4.11
LCD_VLCD: C298.1 J4.1
LCD_VREF: C299.1 J4.12
LED_A1_N: D6.17(A1) U21.R2(PH1)
LED_A2_N: D6.12(A2) U21.C10(PN0)
LED_B1_N: D6.16(B1) U21.R1(PH2)
LED_B2_N: D6.11(B2) U21.B11(PN1)
LED_C1_N: D6.4(C1) U21.T1(PH3)
LED_C2_N: D6.9(C2) U21.A11(PN2)
LED_D1_N: D6.2(D1) U21.R3(PH4)
LED_D2_N: D6.7(D2) U21.B10(PN3)
LED_DP1_N: D6.5(DP1) U21.V2(PH7)
LED_DP2_N: D6.10(DP2) U21.U12(PN7)
LED_E1_N: D6.1(E1) U21.T2(PH5)
LED_E2_N: D6.6(E2) U21.A10(PN4)
LED_F1_N: D6.19(F1) U21.P4(PH0)
LED_F2_N: D6.14(F2) U21.B9(PN5)
LED_G1_N: D6.20(G1) U21.U2(PH6)
LED_G2_N: D6.15(G2) U21.T12(PN6)
LED_P3V3_BT_R: D3.A R12.1
NMOS_D: Q29.D(DRAIN) Q30.D(DRAIN)
PD_EEPROM_WC: R789.1 U16.7(~{WC})
PU_25M_BMC_CLK_EN_R: OSC1.1(OE) R51.2
PWR_BTN: R78.2 U21.F18(PJ4)
PWR_BTN_R: C21.2 R78.1 R944.1 S1.3 S1.4
REV_ID_0: R920.1 R921.2 U21.G19(PL5)
REV_ID_1: R922.1 R923.2 U21.H18(PL4)
RST_BTN: R725.2 U21.C6(PB4_AIN10)
RST_BTN_R: C244.2 R725.1 R910.1 S2.3 S2.4
RST_LCD_N: J4.30 U21.E17(PJ5)
RST_N: C252.1 R730.2 U10.5(RESET)
SEG_SEL_1: D6.3(COM_DIG1_1) D6.18(COM_DIG1_2) R758.1
SEG_SEL_2: D6.8(COM_DIG2_1) D6.13(COM_DIG2_2) R759.1
SET_BAUD_RATE: R10.2 U10.4(GPIO7)
SET_BT_MASTER: R11.2 U10.3(GPIO6)
SET_BT_MODE: R2.2 U10.20(GPIO3)
SMB_SCL: R926.2 U16.6(SCL) U21.A17(PB2_I2C0SCL)
SMB_SCL_R: R925.2 R926.1 U15.5(SSRX-)
SMB_SDA: R927.2 U16.5(SDA) U21.B17(PB3_I2C0SDA)
SMB_SDA_R: R924.2 R927.1 U15.6(SSRX+)
SPI_BMC_LCD_CS_N: J4.19 R79.2
SPI_BMC_LCD_CS_N_R: R79.1 U21.E2(PQ1)
SPI_BMC_LCD_SCK: J4.22 R516.2
SPI_BMC_LCD_SCK_R: R516.1 U21.E3(PQ0)
SPI_BMC_LCD_SDI: J4.20 R513.2
SPI_BMC_LCD_SDI_R: R513.1 U21.H4(PQ2)
SPI_BMC_LCD_SDO: J4.21 R72.2
SPI_BMC_LCD_SDO_R: R72.1 U21.M4(PQ3)
SUPPLY_INPUT: C336.1 R941.1 U24.5(BAT)
TP_CBUS0: U5.23(CBUS0)
TP_CBUS1: U5.22(CBUS1)
TP_CBUS2: U5.13(CBUS2)
TP_CBUS3: U5.14(CBUS3)
TP_CBUS4: U5.12(CBUS4)
TP_CTS_N: U5.11(CTS_N)
TP_DCD_N: U5.10(DCD_N)
TP_DSR_N: U5.9(DSR_N)
TP_DTR_N: U5.2(DTR_N)
TP_LCD_INT_N: J4.29
TP_NC0: U5.8(NC0)
TP_NC1: U5.24(NC1)
TP_OSCI: U5.27(OSCI)
TP_OSCO: U5.28(OSCO)
TP_RI_N: U5.6(RI_N)
TP_RTS_N: U5.3(RTS_N)
TP_SPI_CLK: U10.6(SPI_CLK)
TP_SPI_CS: U10.23(SPI_CSB)
TP_SPI_MI: U10.24(SPI_MISO)
TP_SPI_MO: U10.2(SPI_MOSI)
TP_VBAT: U21.P19(VBAT)
UART_CH_SEL: C332.2 R880.2 R888.1 SW5.3 SW5.4
UART_CH_SEL_BIC: R888.2 R912.1 U21.F16(PJ3)
UART_CTS: R731.2 U10.16(UART_CTS)
UART_GATE: Q5.2(G1) Q5.5(G2) R357.2 R358.1
UART_RTS: R731.1 U10.15(UART_RTS)
UART_TI_R_RXD: R871.1 U21.J1(PK0_AIN16)
UART_TI_R_TXD: R870.1 U21.J2(PK1_AIN17)
UART_TI_RXD: CN1.3(D+) R871.2
UART_TI_TXD: CN1.2(D-) R870.2
USB2_DN: J1.2(D-) U15.2(D-)
USB2_DN_MICRO: J2.2(D-) U5.16(USBDM)
USB2_DP: J1.3(D+) U15.3(D+)
USB2_DP_MICRO: J2.3(D+) U5.15(USBDP)
VOLTAGE_SENSE: R942.2 U24.6(V-)
N17920453: R76.2 S1.1 S1.2
N17920501: R724.2 S2.1 S2.2
N18231426: R911.2 R913.1 SW5.1 SW5.2
N18390536: D15.A R930.1

Not connected (* = marked no-connect by the designer): DM8 1; DM9 1; H2 1(GND); H3 1(GND); H4 1(GND); H5 1(GND); J2 4(ID)*; J4 17 18; TP7 1; U10 7(PCM_CLK)* 8(PCM_SYNC)* 9(PCM_IN)* 10(PCM_OUT)* 17(USB_D+)* 18(USB_D-)* 19(GPIO2) 30(AIO0)* 31(GPIO8)* 32(GPIO9)* 33(GPIO10)* 34(GPIO11)* 35(AIO1)*; U21 A4(PD4_AIN7)* A5(PE4_AIN9)* A7(PE6_AIN20)* A8(PP7_AIN22)* A13(PQ4)* A14(PS3)* A16(PB0_USB0ID)* B2(PD7_AIN4)* B3(PD6_AIN5)* B4(PD5_AIN6)* B5(PE5_AIN8)* B6(PB5_AIN11)* B8(PP6_AIN23)* B12(PP5)* B13(PP2)* B14(PS2)* B16(PB1_USB0VBUS)* B18(PL7_USB0DM)* C1(PD1_AIN14)* C2(PD0_AIN15)* C5(NC) C8(PJ0)* C12(PP3)* C18(PL6_USB0DP)* D1(PD3_AIN12)* D2(PD2_AIN13)* D6(PP0_C2+)* D7(PP1_C2-)* D8(PP4)* D12(PS0)* D13(PS1)* D19(OSC1) E13(NC) E18(PT2)* F1(PB7)* F2(PB6)* F17(PT3)* G1(PE2_AIN1)* G2(PE3_AIN0)* G15(PM5)* G16(PL0)* G18(PL2)* H2(PE1_AIN2)* H3(PE0_AIN3)* H17(PJ2)* H19(PL1)* J18(PL3)* K1(PK2_AIN18)* K2(PK3_AIN19)* K3(PC7_C0-)* K5(PJ7)* K15(PG5)* K17(PG4)* K18(PM0)* K19(PM1)* L2(PC6_C0+)* L18(PM2)* L19(PM3)* M1(PC5_C1+)* M2(PC4_C1-)* M3(PQ7)* M16(PG3)* M17(HIB#) M18(PM4)* N1(PJ6)* N2(PR2)* N4(PR1)* N5(PR0)* N15(PG0)* N18(PM7)* N19(PM6)* P2(PR5)* P3(PR4)* R7(PA7)* R13(PS7)* T6(PA2_SSI0CLK)* T7(PF3)* T8(PF6)* T14(PG1)* T18(XOSC0) T19(XOSC1) U5(PA3_SSI0FSS)* U6(PF0)* U8(PF7)* U10(PS6)* U14(PG7)* U15(PQ6)* U18(WAKE#) V5(PA6)* V6(PF1)* V8(PR3)* V9(PS4)* V10(PT1)* V11(PG2)* V12(PG6)* V13(NC) V14(NC) V15(NC) V17(PK5)* V18(NC) V19(NC) W4(PA5_SSI0XDAT1)* W7(PF5)* W9(PR6)* W12(PQ5)* W13(NC) W15(NC) W16(PK7)* W18(NC) W19(NC); U24 1(NC1)*

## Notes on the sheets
sheet 1
- Model : USB Bluetooth Debug Card
sheet 2
- TABLE OF CONTENTS
- Page1    TITLE
  Page2    TABLE OF CONTENTS
  Page3    BLOCK DIAGRAM
  Page4    POWER BLOCK DIAGRAM
  Page5    UART BLOCK DIAGRAM
  Page6    SMBUS BLOCK DIAGRAM
  Page7    COM TO USB/ BT MODULE
  Page8    PORT 80 LED
  Page9    LCD PANEL
  Page10   MECHANICAL & DUMMY SYMBOL
  Page11   P5V TO P3V3/SUPER CAP
  Page12   SNOWFLAKE 1
  Page13   SNOWFLAKE 2
sheet 3
- BLOCK DIAGRAM
sheet 7
- PWR Button Color: Red
- RST Button Color: Black
sheet 8
- LCD FPC connector
- LCD Backlight connector
- Battery CONN
- Battery Protect IC
- OVP: 4.275V
  UVP: 2.8V
sheet 9
- REV ID 01
- Battery Charge LED(Blue)
- Battery Low Power LED(Red)
- 5 Ways Button
- Default : Host console
  Falling edge trigger among host console =>
  BMC debug console => midplane console
- UART Select Button Color: Brown
- MCU Heartbeat LED
- MCU Debug Micro USB CONN
- SNOWFLAKE_1
sheet 10
- SNOWFLAKE_2
sheet 11
- LASER MARK
- PB-E1
- WEEE
- ME parts brkt
- LCD Rubber
- LCD HOLE
sheet 12
- Address 0xA8 [ 1010 E2 E1 E0 0]
- Connect with MB
- USB 3.0 CONN
- FRU
- USB 2.0 CONN
- FTDI (COM to USB)
- BLUETOOTH RN42
- LED IF MAX=25mA
- LED VF MAX=2.35V
- BT Function LED
  BT Linked: LED Bright
  BT No Link: LED Flash
- Micro USB 2.0 CONN
